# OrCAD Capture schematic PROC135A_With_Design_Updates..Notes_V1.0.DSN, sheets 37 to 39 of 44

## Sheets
37 37. CSI INTERFACE: size C; title: CSI INTERFACE
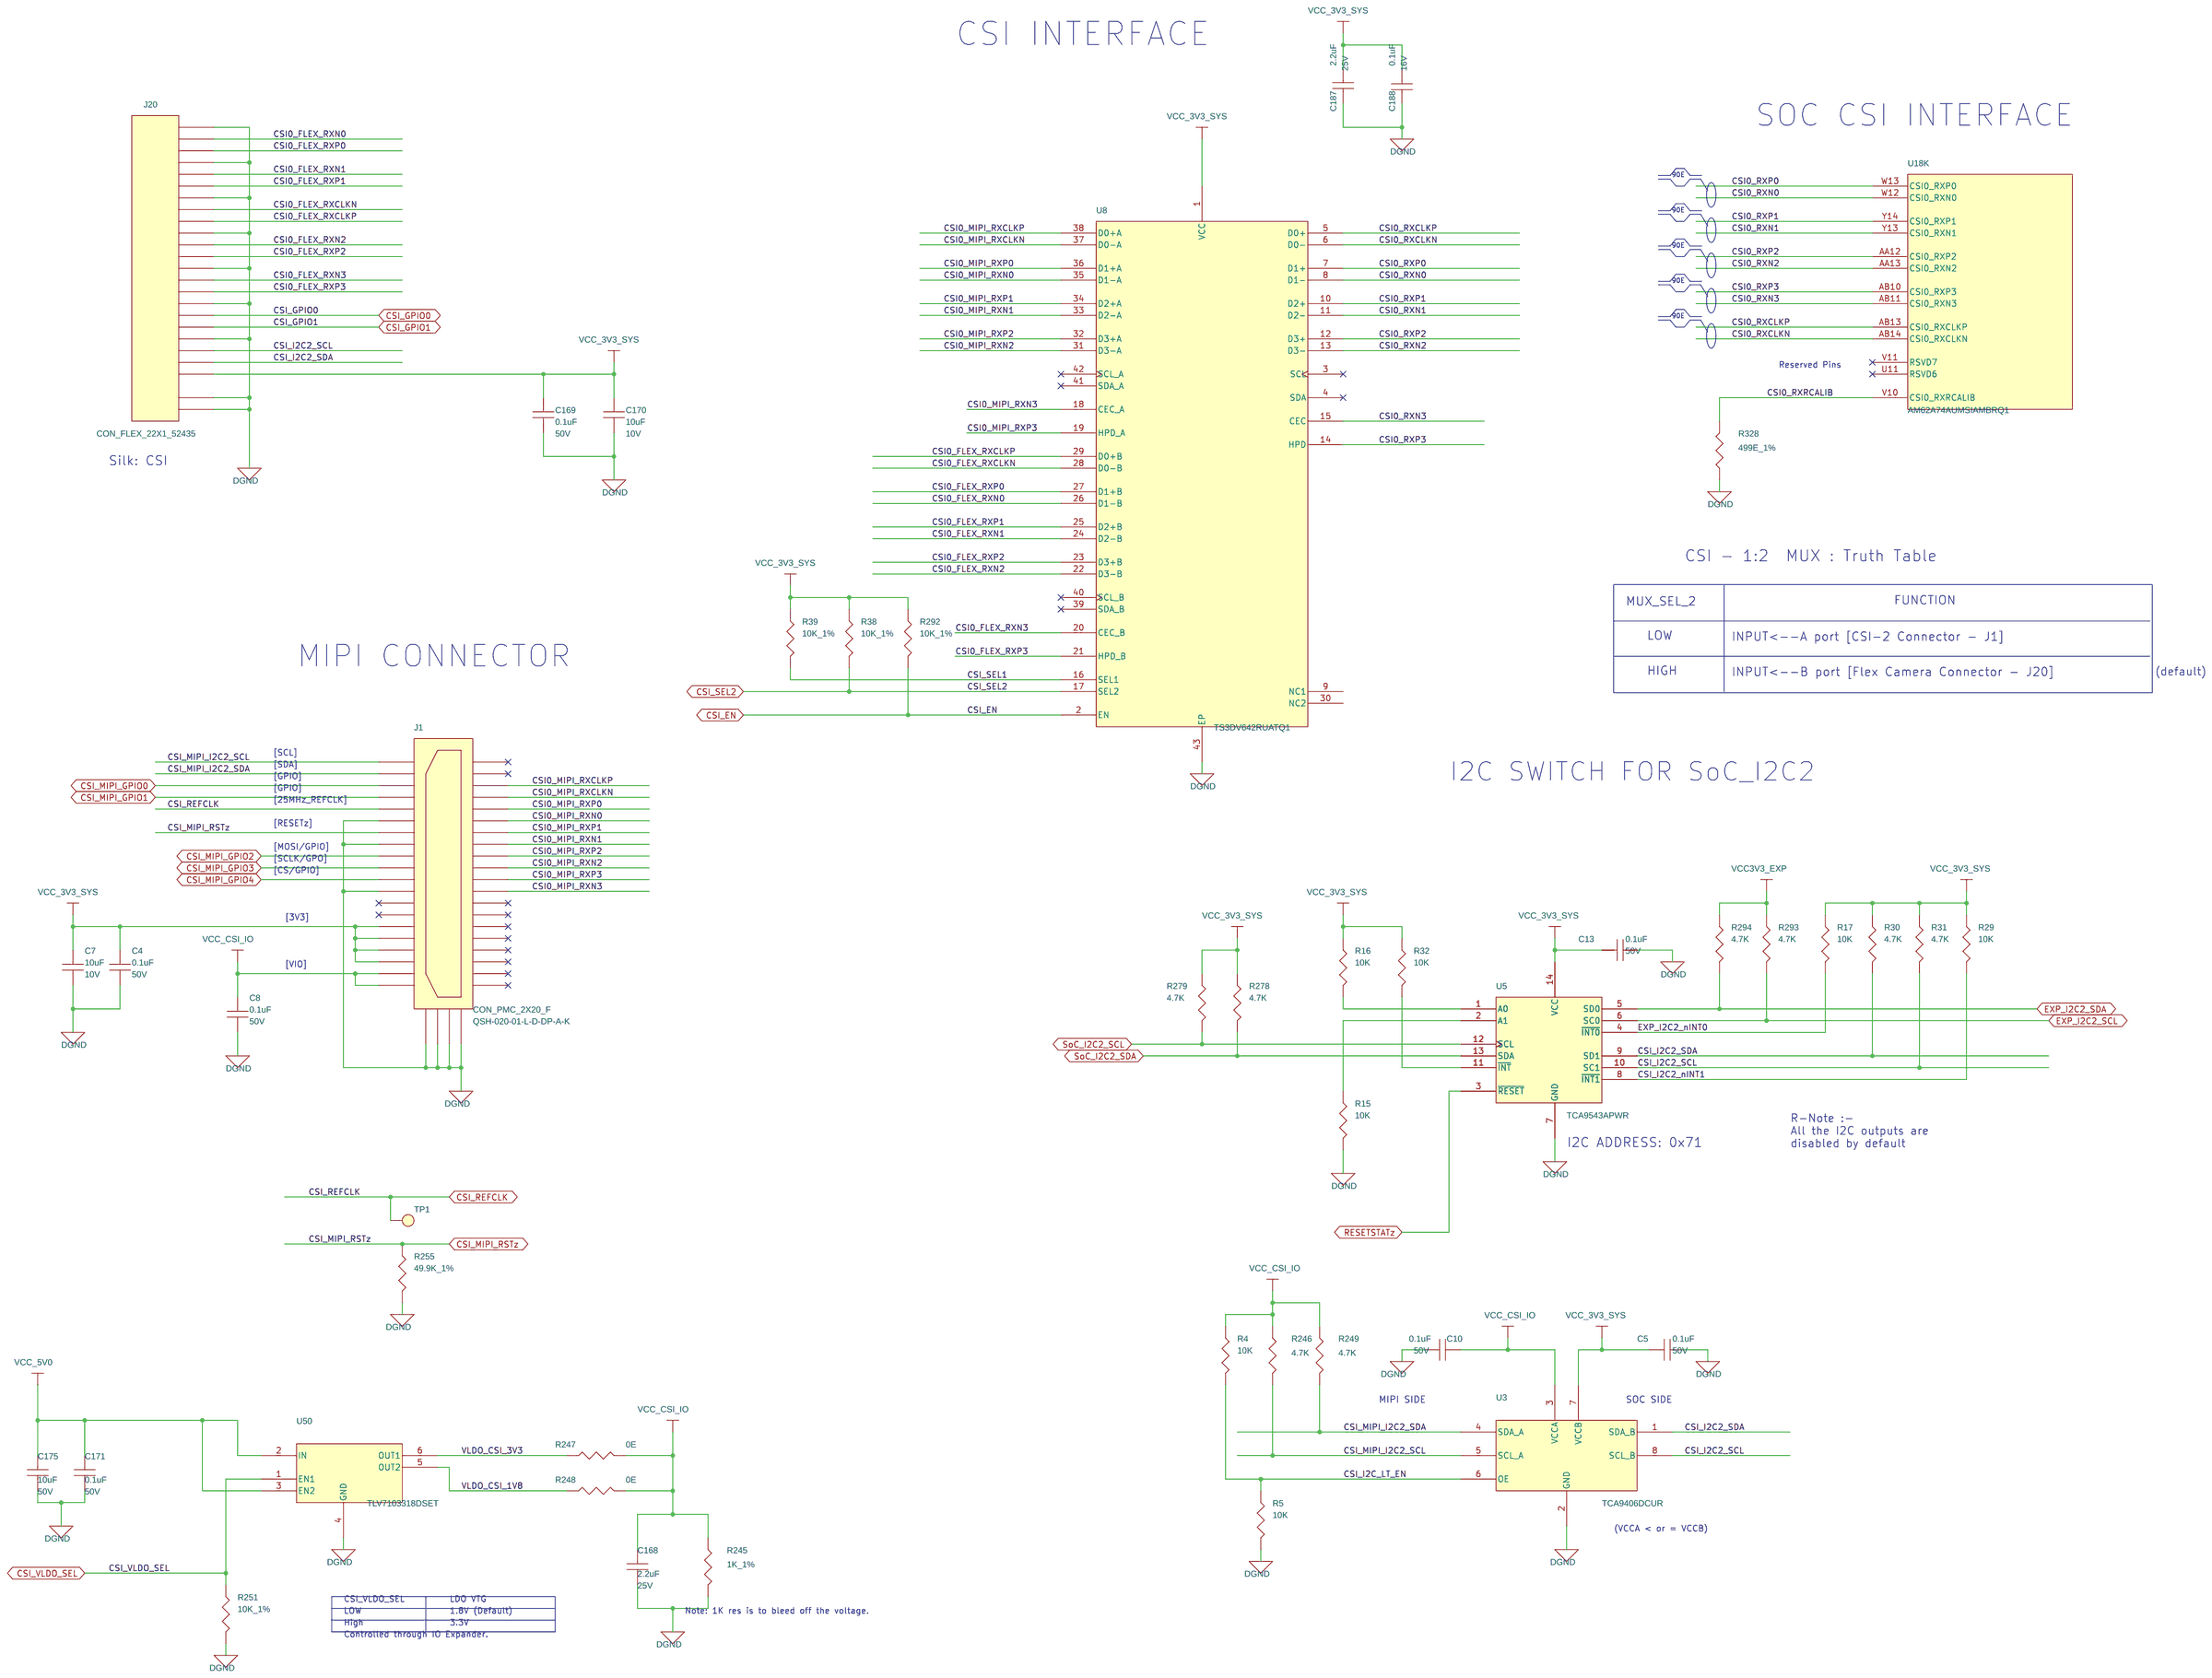
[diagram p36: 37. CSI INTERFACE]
38 38. AUDIO CODEC: size C; title: AUDIO CODEC
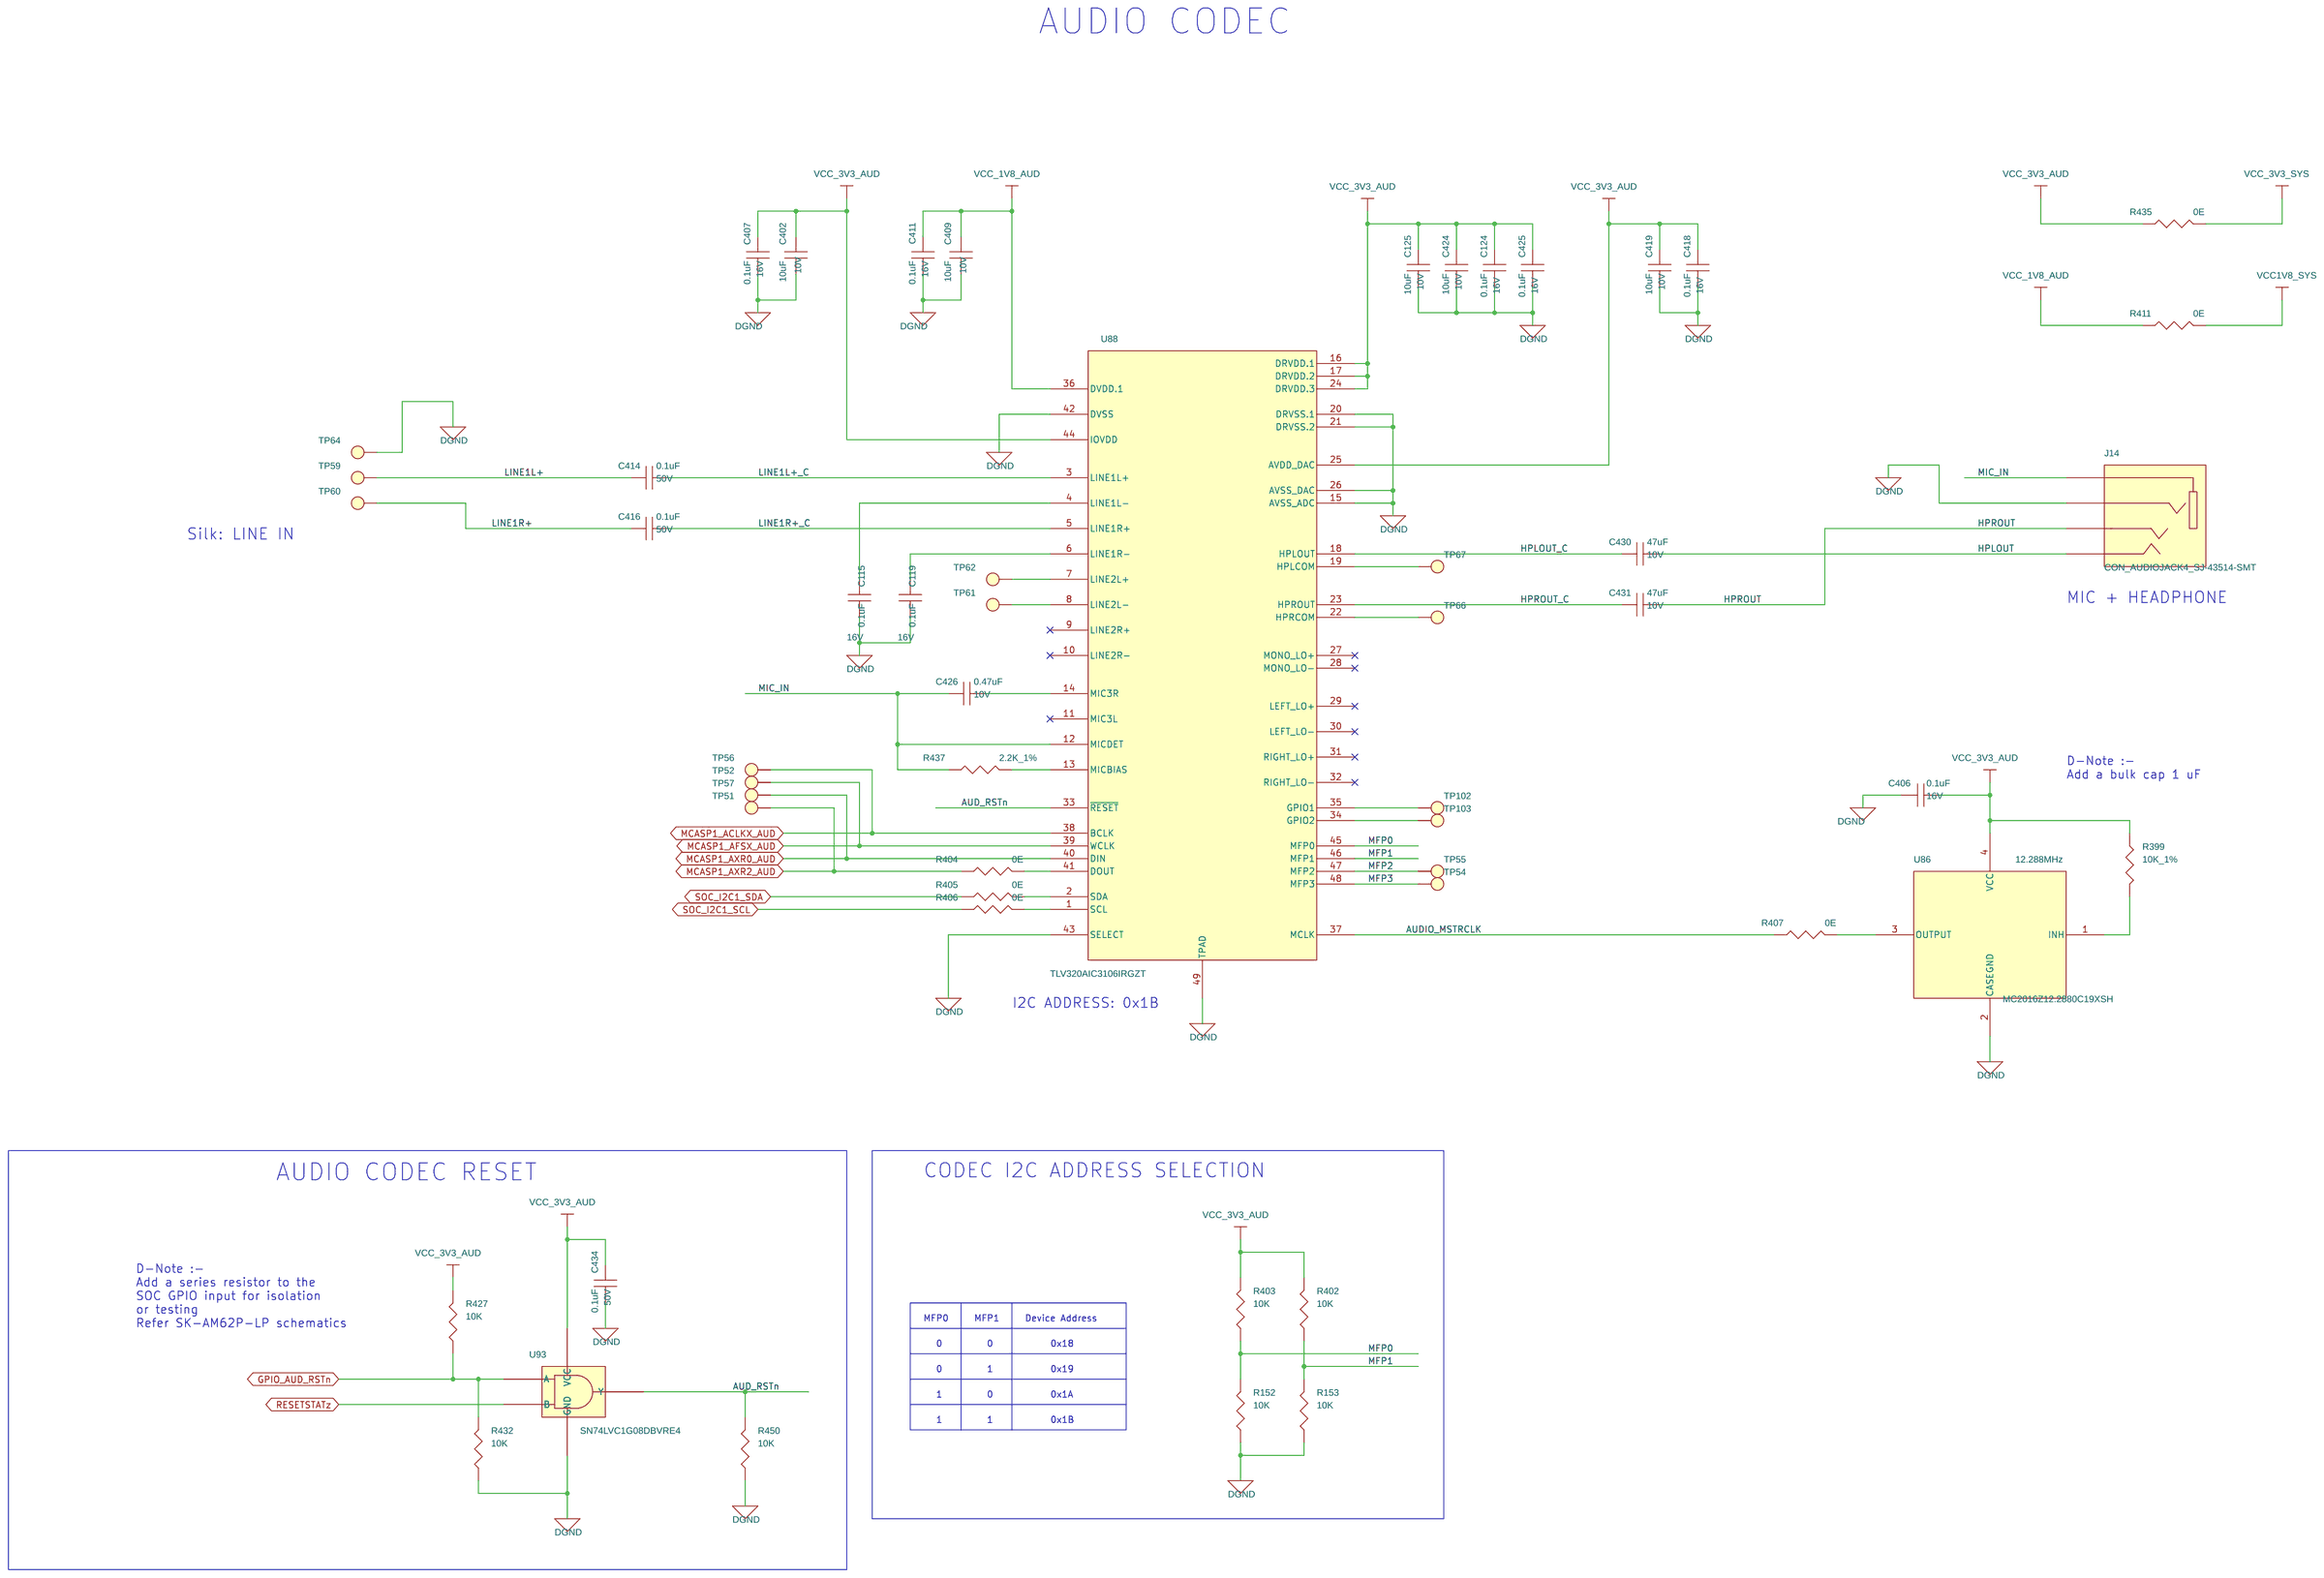
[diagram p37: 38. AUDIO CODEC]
39 39. IO EXPANDER: size C; title: IO EXPANDER
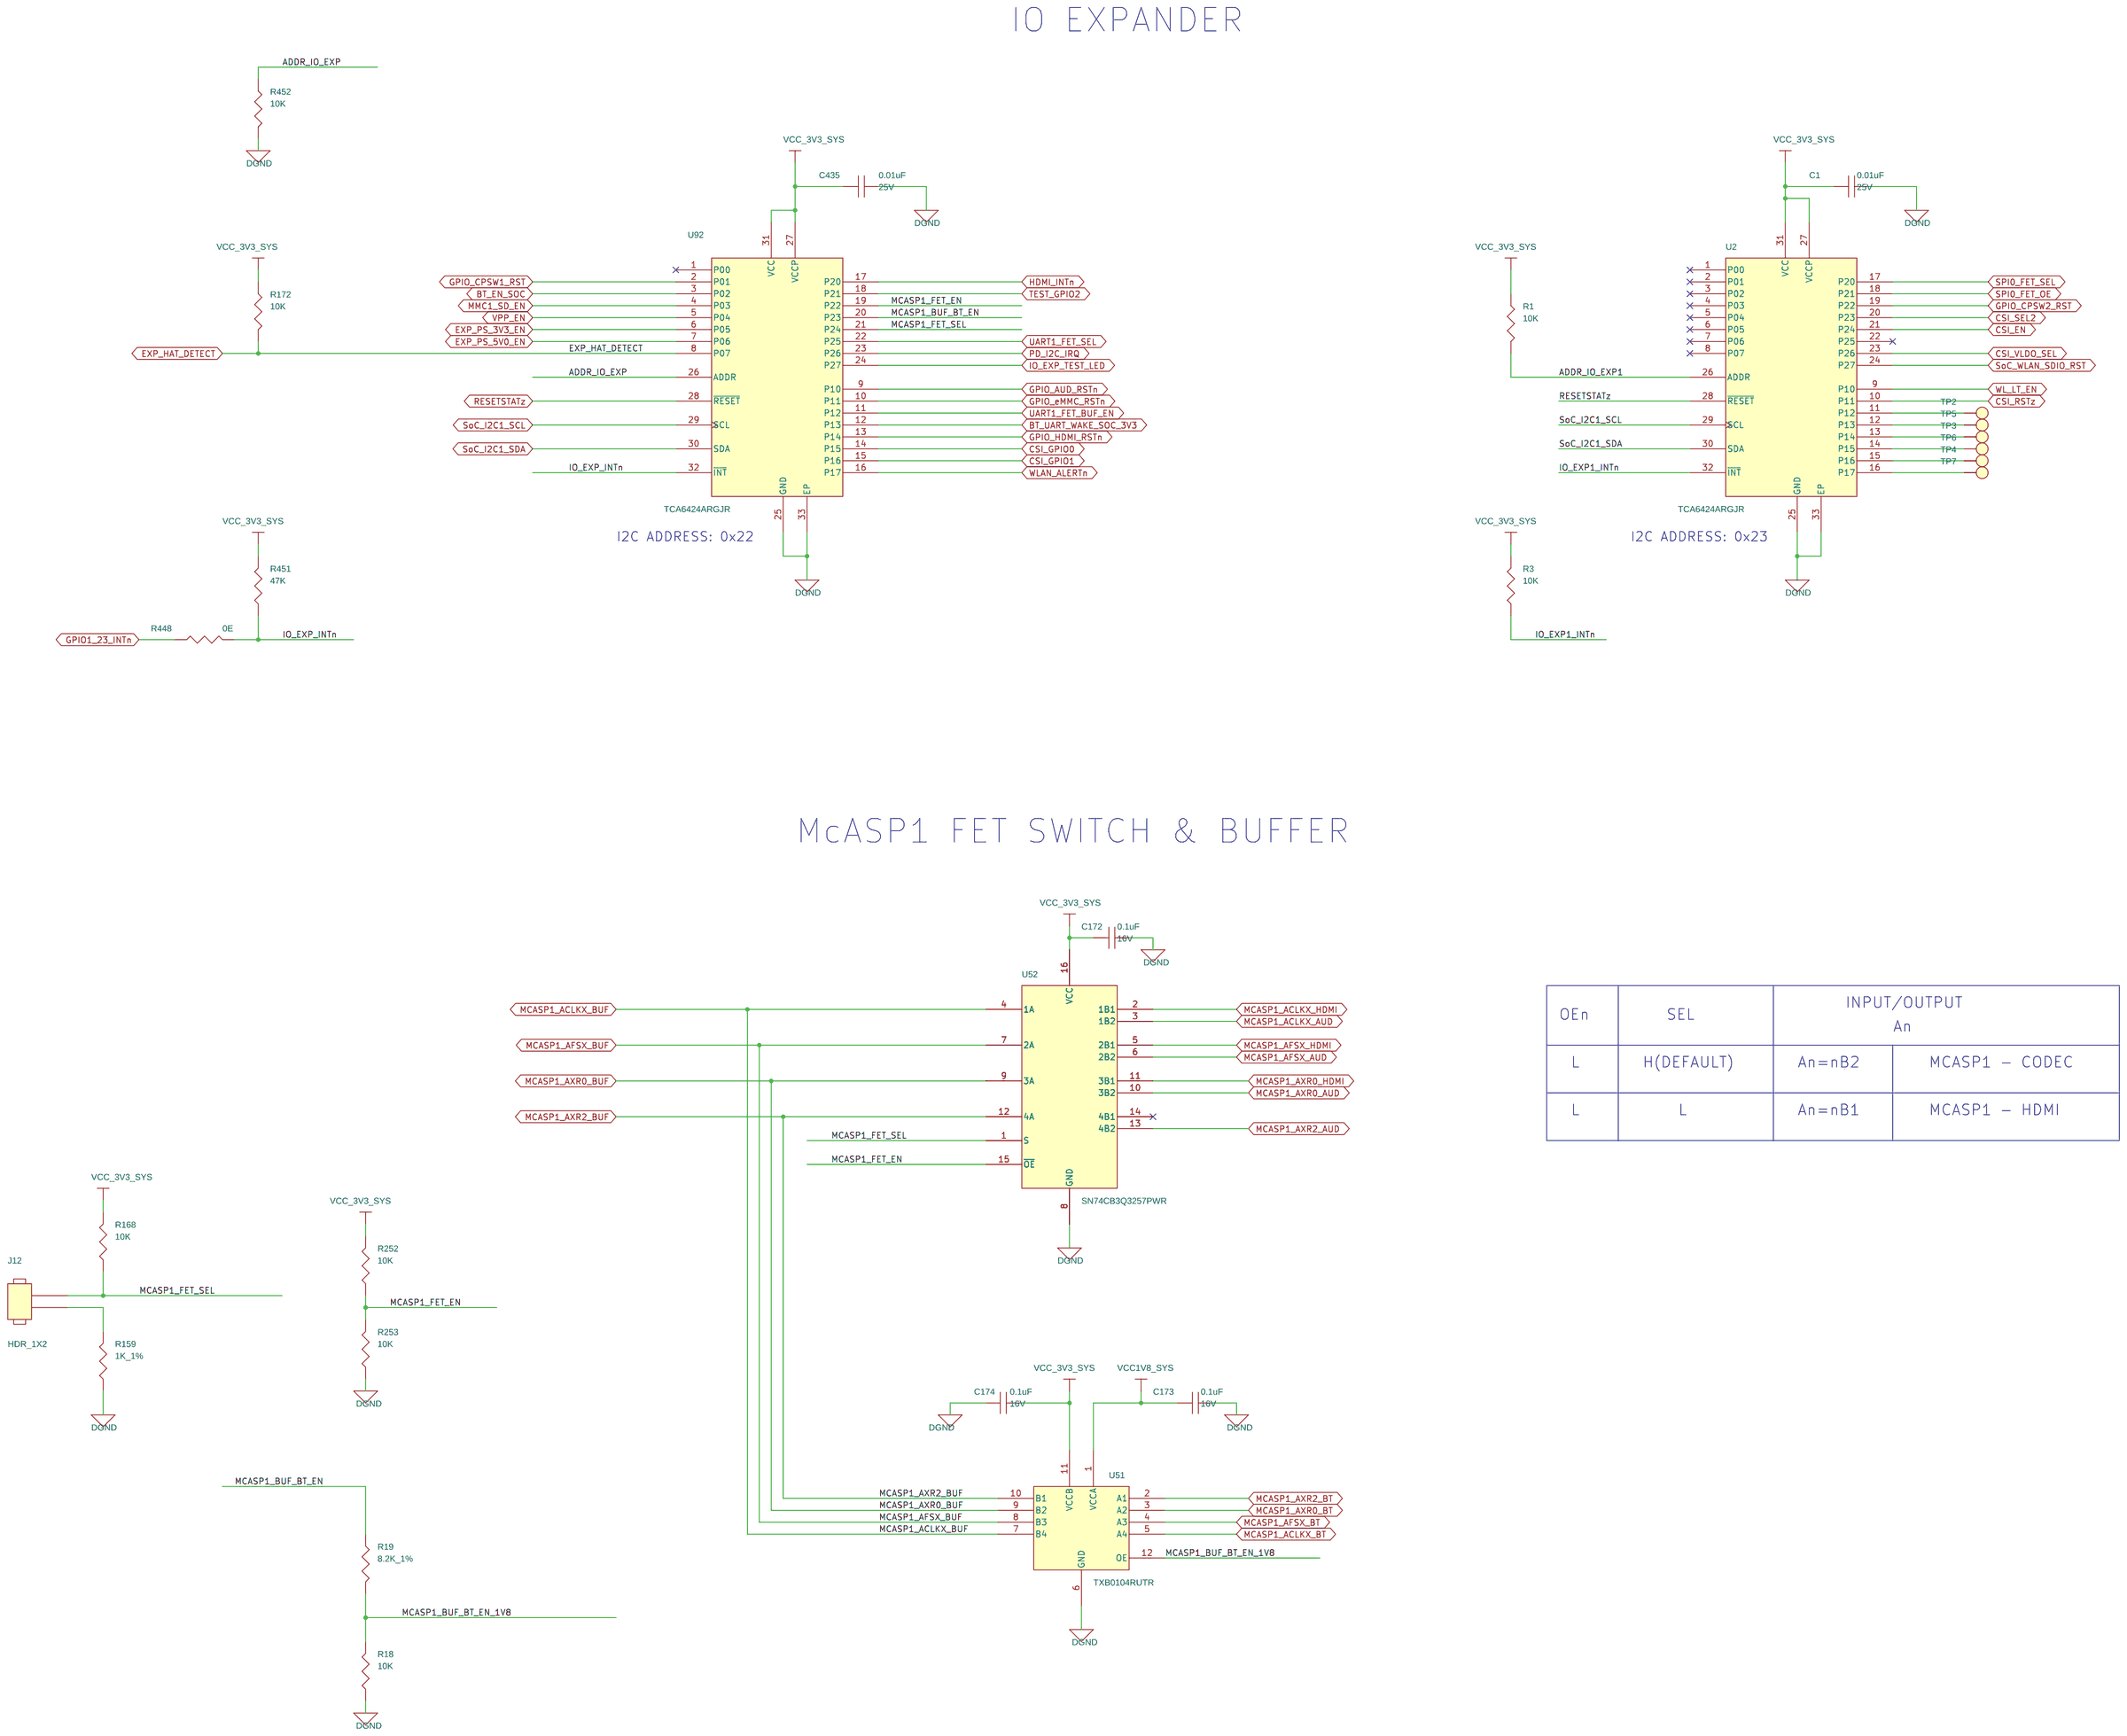
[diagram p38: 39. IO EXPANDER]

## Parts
sheet 37. CSI INTERFACE
C4  0.1uF  [CAP0402_0-75]
C5  0.1uF  [CAP0402_0-75]
C7  10uF  [CAP0402_0-75]
C8  0.1uF  [CAP0402_0-75]
C10  0.1uF  [CAP0402_0-75]
C13  0.1uF  [CAP0402_0-75]
C168  2.2uF  [CAP0402_0-75]
C169  0.1uF  [CAP0402_0-75]
C170  10uF  [CAP0402_0-75]
C171  0.1uF  [CAP0402_0-75]
C175  10uF  [CAP0805_1-5]
C187  2.2uF  [CAP0402_0-75]
C188  0.1uF  [CAP0201_0-5]
J1  CON_PMC_2X20_F  [CON_PMC2X20_QSH-020-01-D-DP-A_S_S_S_3-4]
J20  CON_FLEX_22X1_52435  [CON_FLEX22X1_52435_S_R_S]
R4  10K  [RES0201_0-5]
R5  10K  [RES0201_0-5]
R15  10K  [RES0201_0-5]
R16  10K  [RES0201_0-5]
R17  10K  [RES0201_0-5]
R29  10K  [RES0201_0-5]
R30  4.7K  [RES0201_0-5]
R31  4.7K  [RES0201_0-5]
R32  10K  [RES0201_0-5]
R38  10K_1%  [RES0402_0-5]
R39  10K_1%  [RES0402_0-5]
R245  1K_1%  [RES0402_0-5]
R246  4.7K  [RES0201_0-5]
R247  0E  [RES0402_0-5]
R248  0E  [RES0402_0-5]
R249  4.7K  [RES0201_0-5]
R251  10K_1%  [RES0402_0-5]
R255  49.9K_1%  [RES0402_0-5]
R278  4.7K  [RES0201_0-5]
R279  4.7K  [RES0201_0-5]
R292  10K_1%  [RES0402_0-5]
R293  4.7K  [RES0201_0-5]
R294  4.7K  [RES0201_0-5]
R328  499E_1%  [RES0402_0-5]
TP1  TP20_SMD  [TP20_SMD]
U3  TCA9406DCUR  [VSSOP8_19-68_85X95]
U5  TCA9543APWR  [TSSOP14_25-59_205X180_1-2]
U8  TS3DV642RUATQ1  [TQFN42_19-68_140X360_0-8]
U50  TLV7103318DSET  [WSON6_19-68_60X60]
sheet 38. AUDIO CODEC
C115  0.1uF  [CAP0201_0-5]
C119  0.1uF  [CAP0201_0-5]
C124  0.1uF  [CAP0201_0-5]
C125  10uF  [CAP0402_0-75]
C402  10uF  [CAP0402_0-75]
C406  0.1uF  [CAP0201_0-5]
C407  0.1uF  [CAP0201_0-5]
C409  10uF  [CAP0402_0-75]
C411  0.1uF  [CAP0201_0-5]
C414  0.1uF  [CAP0402_0-75]
C416  0.1uF  [CAP0402_0-75]
C418  0.1uF  [CAP0201_0-5]
C419  10uF  [CAP0402_0-75]
C424  10uF  [CAP0402_0-75]
C425  0.1uF  [CAP0201_0-5]
C426  0.47uF  [CAP0402_0-75]
C430  47uF  [CAP1206_2]
C431  47uF  [CAP1206_2]
C434  0.1uF  [CAP0402_0-75]
J14  CON_AUDIOJACK4_SJ-43514-SMT  [CON_AV4_SJ-43514-SMT_S_R_S_5-1]
R152  10K  [RES0201_0-5]
R153  10K  [RES0201_0-5]
R399  10K_1%  [RES0201_0-5]
R402  10K  [RES0201_0-5]
R403  10K  [RES0201_0-5]
R404  0E  [RES0201_0-5]
R405  0E  [RES0201_0-5]
R406  0E  [RES0201_0-5]
R407  0E  [RES0201_0-5]
R411  0E  [RES0402_0-5]
R427  10K  [RES0201_0-5]
R432  10K  [RES0201_0-5]
R435  0E  [RES0402_0-5]
R437  2.2K_1%  [RES0201_0-5]
R450  10K  [RES0201_0-5]
TP51  TP20_SMD  [TP20_SMD]
TP52  TP20_SMD  [TP20_SMD]
TP54  TP20_SMD  [TP20_SMD]
TP55  TP20_SMD  [TP20_SMD]
TP56  TP20_SMD  [TP20_SMD]
TP57  TP20_SMD  [TP20_SMD]
TP59  THRU HOLE  [TP_40X65]
TP60  THRU HOLE  [TP_40X65]
TP61  TP20_SMD  [TP20_SMD]
TP62  TP20_SMD  [TP20_SMD]
TP64  THRU HOLE  [TP_40X65]
TP66  TP20_SMD  [TP20_SMD]
TP67  TP20_SMD  [TP20_SMD]
TP102  TP20_SMD  [TP20_SMD]
TP103  TP20_SMD  [TP20_SMD]
U86  12.288MHz  [OSC4_KC2016K_80X60_SMD_0-8]
U88  TLV320AIC3106IRGZT  [VQFN48_19-68_285X285]
U93  SN74LVC1G08DBVRE4  [SOT23-5]
sheet 39. IO EXPANDER
C1  0.01uF  [CAP0201_0-5]
C172  0.1uF  [CAP0201_0-5]
C173  0.1uF  [CAP0201_0-5]
C174  0.1uF  [CAP0201_0-5]
C435  0.01uF  [CAP0201_0-5]
J12  HDR_1X2  [HDR_1X2_90120-0122_S_T_5-6]
R1  10K  [RES0201_0-5]
R3  10K  [RES0201_0-5]
R18  10K  [RES0201_0-5]
R19  8.2K_1%  [RES0201_0-5]
R159  1K_1%  [RES0402_0-5]
R168  10K  [RES0201_0-5]
R172  10K  [RES0201_0-5]
R252  10K  [RES0201_0-5]
R253  10K  [RES0201_0-5]
R448  0E  [RES0201_0-5]
R451  47K  [RES0201_0-5]
R452  10K  [RES0201_0-5]
TP2  TP20_SMD  [TP20_SMD]
TP3  TP20_SMD  [TP20_SMD]
TP4  TP20_SMD  [TP20_SMD]
TP5  TP20_SMD  [TP20_SMD]
TP6  TP20_SMD  [TP20_SMD]
TP7  TP20_SMD  [TP20_SMD]
U2  TCA6424ARGJR  [QFN32_19-68_200X200]
U51  TXB0104RUTR  [UQFN12_TXB0104RUT_70X80_0-6]
U52  SN74CB3Q3257PWR  [TSSOP16_25-59_205X180]
U92  TCA6424ARGJR  [QFN32_19-68_200X200]
sheet 41. OSCILLATOR
U18  AM62A74AUMSIAMBRQ1  [FBGA484_31-49_710X710_2-7]  (sections A,B,C,D,E,F,G,H,I,J,K,L,M,N,O,P,Q)

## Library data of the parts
C4 C5 C8 C10 C13 C169 C171 = CAP: CAP CERAMIC 0.1uF 50V 10% X7R 0402; Alt_Mfr_name: YAGEO AMERICA; Alt_Mfr_part_number: CC0402KRX5R8BB104; Chkd/date: MANIRAJA/261020; Crtd /date: ALVY/211020; Custom_Duty: 15%; Customs_HS_Code: 85322990; Distributor_name: DIGIKEY; Distributor_part_number: 490-10700-1-ND; Footprint Path: Y:\MIS_DATABASE\Library\ALTIUM_TOOL\PCB_FOOTPRINTS\Altium_Footprint_Lib.PcbLib; Height: 0.55MM; Library Path: Y:\MIS_DATABASE\Library\ALTIUM_TOOL\SCHEMATICS_PARTS\MS_DISCRETE_Library.schlib; Mfr_name: MURATA; Mfr_part_number: GRM155R71H104KE14D; Mistral Part No: 120011100014-R; Package: 0402; Part_type: CAPACITORS\CERAMIC; Project: J7_CP; RoHS: RoHS; Temperature: -55°C+125°C; Tolerance: 10%; Voltage: 50V; Wattage: NA; Weight: 3.1mg; Datasheet: Y:\MIS_DATABASE\DATASHEETS\CAPACITORS\GRM155R71H104KE14.PDF
C7 C125 C170 C402 C409 C419 C424 = CAP: CAP CERAMIC 10uF 10V 20% X5R 0402; Chkd/date: MANIRAJA/300520; Crtd /date: ALVY/260520; Custom_Duty: 15%; Customs_HS_Code: 85322990; Distributor_name: DIGIKEY; Distributor_part_number: 490-GRM155R61A106ME11DTR-ND; Footprint Path: Y:\MIS_DATABASE\Library\ALTIUM_TOOL\PCB_FOOTPRINTS\Altium_Footprint_Lib.PcbLib; Height: 0.55MM; Library Path: Y:\MIS_DATABASE\Library\ALTIUM_TOOL\SCHEMATICS_PARTS\MS_DISCRETE_Library.schlib; Mfr_name: MURATA; Mfr_part_number: GRM155R61A106ME11D; Mistral Part No: 120013110019-R; Package: 0402; Part_type: CAPACITORS\CERAMIC; Project: QCS610_NANOSOM; RoHS: RoHS; Temperature: -55°C+85°C; Tolerance: 20%; Voltage: 10V; Wattage: NA; Weight: 3.1mg; Datasheet: Y:\MIS_DATABASE\DATASHEETS\CAPACITORS\MURATA-GXX-SER_NOV17.PDF
C168 = CAP: CAP CERAMIC 2.2uF 25V 10% X5R 0402; Chkd/date: ALVY/010721; Crtd /date: MANIRAJA/010721; Custom_Duty: 15%; Customs_HS_Code: 85322990; Distributor_name: DIGIKEY; Distributor_part_number: 490-12703-1-ND; Footprint Path: Y:\MIS_DATABASE\Library\ALTIUM_TOOL\PCB_FOOTPRINTS\Altium_Footprint_Lib.PcbLib; Height: 0.70MM; Library Path: Y:\MIS_DATABASE\Library\ALTIUM_TOOL\SCHEMATICS_PARTS\MS_DISCRETE_Library.schlib; Manufacturer: MURATA; Mfr_name: MURATA; Mfr_part_number: GRM155R61E225KE11D; Mistral Part No: 120015120001-R; Package: 0402; Part_type: CAPACITORS\CERAMIC; Project: TI_AM263X_CC; RoHS: RoHS; Temperature: -55°C+85°C; Tolerance: 10%; Voltage: 25V; Wattage: NA; Weight: 1.5mg; Datasheet: Y:\MIS_DATABASE\DATASHEETS\CAPACITORS\GRM155R61E225KE11.PDF
C175 = CAP: CAP CERAMIC 10uF 50V 10% X5R 0805; Chkd/date: MANIRAJA/010321; Crtd /date: ALVY/010321; Custom_Duty: 15%; Customs_HS_Code: 85322990; Distributor_name: DIGIKEY; Distributor_part_number: 490-18663-1-ND; Footprint Path: Y:\MIS_DATABASE\Library\ALTIUM_TOOL\PCB_FOOTPRINTS\Altium_Footprint_Lib.PcbLib; Height: 1.45MM; Library Path: Y:\MIS_DATABASE\Library\ALTIUM_TOOL\SCHEMATICS_PARTS\MS_DISCRETE_Library.schlib; Manufacturer: MURATA; Mfr_name: MURATA; Mfr_part_number: GRM21BR61H106KE43L; Mistral Part No: 120021030002-R; Package: 0805; Part_type: CAPACITORS\CERAMIC; Project: J7ES_SK_BRD; RoHS: RoHS; Temperature: -55°C+85°C; Tolerance: 10%; Voltage: 50V; Wattage: NA; Weight: 6.4mg; Datasheet: Y:\MIS_DATABASE\DATASHEETS\CAPACITORS\GRM21BR61H106KE43.PDF
C187 = CAP: CAP CERAMIC 2.2uF 25V 10% X5R 0402; Chkd/date: ALVY/010721; Crtd /date: MANIRAJA/010721; Custom_Duty: 15%; Customs_HS_Code: 85322990; Distributor_name: DIGIKEY; Distributor_part_number: 490-12703-1-ND; Footprint Path: Y:\MIS_DATABASE\Library\ALTIUM_TOOL\PCB_FOOTPRINTS\Altium_Footprint_Lib.PcbLib; Height: 0.70MM; Library Path: Y:\MIS_DATABASE\Library\ALTIUM_TOOL\SCHEMATICS_PARTS\MS_DISCRETE_Library.schlib; Mfr_name: MURATA; Mfr_part_number: GRM155R61E225KE11D; Mistral Part No: 120015120001-R; Package: 0402; Part_type: CAPACITORS\CERAMIC; Project: TI_AM263X_CC; RoHS: RoHS; Temperature: -55°C+85°C; Tolerance: 10%; Voltage: 25V; Wattage: NA; Weight: 1.5mg; Datasheet: Y:\MIS_DATABASE\DATASHEETS\CAPACITORS\GRM155R61E225KE11.PDF
C172-C174 C188 = CAP: CAP CERAMIC 0.1uF 16V 10% X5R 0201; Alt_Mfr_name: YAGEO AMERICA; Alt_Mfr_part_number: CC0402KRX5R8BB104; Chkd/date: MANIRAJA/230118; Crtd /date: MANIRAJA/230118; Custom_Duty: 15%; Customs_HS_Code: 85322990; Distributor_name: DIGIKEY; Distributor_part_number: 490-14305-1-ND; Footprint Path: Y:\MIS_DATABASE\Library\ALTIUM_TOOL\PCB_FOOTPRINTS\Altium_Footprint_Lib.PcbLib; Height: 0.33MM; Library Path: Y:\MIS_DATABASE\Library\ALTIUM_TOOL\SCHEMATICS_PARTS\MS_DISCRETE_Library.schlib; Mfr_name: MURATA; Mfr_part_number: GRM033R61C104KE14D; Mistral Part No: 120009030072-R; Package: 0201; Part_type: CAPACITORS\CERAMIC; Project: TI_MAXIE_CPB; RoHS: RoHS; Temperature: -55°C+85°C; Tolerance: 10%; Voltage: 16V; Wattage: NA; Weight: 0.33mg; Datasheet: Y:\MIS_DATABASE\DATASHEETS\CAPACITORS\GRM033R61C104KE14.PDF
J1 = CON_PMC_20X2_F_DP_TI: CON PMC 2X20 0.50MM PITCH FEMALE ST SMD; Chkd/date: MANIRAJA/251018; Crtd /date: ALVY/251018; Custom_Duty: 24%; Customs_HS_Code: 85369090; Distributor_name: DIGIKEY; Distributor_part_number: SAM10648-ND; Footprint Path: Y:\MIS_DATABASE\Library\ALTIUM_TOOL\PCB_FOOTPRINTS\Altium_Footprint_Lib.PcbLib; Height: 3.33MM; Library Path: Y:\MIS_DATABASE\Library\ALTIUM_TOOL\SCHEMATICS_PARTS\MS_CONNECTOR_Library.schlib; Library Ref: CON_PMC_20X2_F_DP; Mfr_name: SAMTEC; Mfr_part_number: QSH-020-01-L-D-DP-A-K; Mistral Part No: 150018100049-R; Package: SMD; Part_type: CONNECTOR\PMC; Project: TI_J7ES_EVM_CP; RoHS: RoHS; Temperature: -55°C+125°C; Tolerance: NA; Voltage: NA; Wattage: NA; Weight: NA; Datasheet: Y:\MIS_DATABASE\DATASHEETS\CONNECTORS\QSH-SERIES.PDF
J20 = CON_22X1_2SH: CON FPC 22X1 0.50MM PITCH TPM RT SMD; Chkd/date: PRAVEEN/090822; Crtd /date: PRAVEEN/090822; Custom_Duty: 24%; Customs_HS_Code: 85369090; Distributor_name: DIGIKEY; Distributor_part_number: WM6753CT-ND; Height: 2.00MM; Mfr_name: MOLEX; Mfr_part_number: 52435-2271; Mistral Part No: 150022080019-R; Package: SMD; Part_type: CONNECTOR\FPC; Project: JHAHP_SVB; RoHS: RoHS; Temperature: -20°C to +85°C; Tolerance: NA; Voltage: NA; Wattage: NA; Datasheet: Y:\MIS_DATABASE\DATASHEETS\CONNECTORS\52435.PDF
R1 R3-R5 R15-R18 R29 R32 R152 R153 R168 R172 R252 R253 R402 R403 R427 R432 R450 R452 = RESISTOR: RES 10K 1/20W 5% 0201; Chkd/date: MANIRAJA/050517; Crtd /date: MANIRAJA/050517; Custom_Duty: 15%; Customs_HS_Code: 85332119; Distributor_name: DIGIKEY; Distributor_part_number: 311-10KNCT-ND; Footprint Path: Y:\MIS_DATABASE\Library\ALTIUM_TOOL\PCB_FOOTPRINTS\Altium_Footprint_Lib.PcbLib; Height: 0.26MM; Library Path: Y:\MIS_DATABASE\Library\ALTIUM_TOOL\SCHEMATICS_PARTS\MS_DISCRETE_Library.schlib; Mfr_name: YAGEO AMERICA; Mfr_part_number: RC0201JR-0710KL; Mistral Part No: 110010070051-R; Package: 0201; Part_type: RESISTORS\FIXED; Project: GOLDEN-I LITE; RoHS: RoHS; Temperature: -55°C+125°C; Tolerance: 5%; Voltage: NA; Wattage: 1/20W; Weight: 0.17mg; Datasheet: Y:\MIS_DATABASE\DATASHEETS\RESISTORS\RCXXXXL-SER_MAR18.PDF
R30 R31 R246 R249 R278 R279 R293 R294 = RESISTOR: RES 4.7K 1/20W 5% 0201; Chkd/date: MANIRAJA/200921; Crtd /date: ALVY/200921; Custom_Duty: 15%; Customs_HS_Code: 85332119; Distributor_name: DIGIKEY; Distributor_part_number: 311-4.7KNCT-ND; Footprint Path: Y:\MIS_DATABASE\Library\ALTIUM_TOOL\PCB_FOOTPRINTS\Altium_Footprint_Lib.PcbLib; Height: 0.26MM; Library Path: Y:\MIS_DATABASE\Library\ALTIUM_TOOL\SCHEMATICS_PARTS\MS_DISCRETE_Library.schlib; Mfr_name: YAGEO AMERICA; Mfr_part_number: RC0201JR-074K7L; Mistral Part No: 110021090007-R; Package: 0201; Part_type: RESISTORS\FIXED; Project: TI_AM62x SKEVM_BRD; RoHS: RoHS; Temperature: -55°C+125°C; Tolerance: 5%; Voltage: NA; Wattage: 1/20W; Weight: 0.17mg; Datasheet: Y:\MIS_DATABASE\DATASHEETS\RESISTORS\RCXXXXL-SER_MAR18.PDF
R38 R39 R251 R292 = RESISTOR: RES 10K 1/10W 1% AUTO 0402; Chkd/date: MANIRAJA/191020; Crtd /date: ALVY/191020; Custom_Duty: 15%; Customs_HS_Code: 85332119; Distributor_name: DIGIKEY; Distributor_part_number: MCS0402-10.0K-MFCT-ND; Footprint Path: Y:\MIS_DATABASE\Library\ALTIUM_TOOL\PCB_FOOTPRINTS\Altium_Footprint_Lib.PcbLib; Height: 0.37MM; Library Path: Y:\MIS_DATABASE\Library\ALTIUM_TOOL\SCHEMATICS_PARTS\MS_DISCRETE_Library.schlib; Manufacturer: VISHAY; Mfr_name: VISHAY; Mfr_part_number: MCS0402MC1002FE000; Mistral Part No: 110020100039-R; Package: 0402; Part_type: RESISTORS\FIXED; Project: MCX_80MHz_ADC_DRIVER; RoHS: RoHS; Temperature: -55°C+175°C; Tolerance: 1%; Voltage: NA; Wattage: 1/10W; Weight: 0.65mg; Datasheet: Y:\MIS_DATABASE\DATASHEETS\RESISTORS\MCTXXXXM-SER.PDF
R159 R245 = RESISTOR: RES 1K 1/10W 1% 0402; Chkd/date: VASANTHA/281216; Crtd /date: MAZHAR/150506; Custom_Duty: 15%; Customs_HS_Code: 85332119; Distributor_name: DIGIKEY; Distributor_part_number: P1.00KLCT-ND; Footprint Path: Y:\MIS_DATABASE\Library\ALTIUM_TOOL\PCB_FOOTPRINTS\Altium_Footprint_Lib.PcbLib; Height: 0.40MM; Library Path: Y:\MIS_DATABASE\Library\ALTIUM_TOOL\SCHEMATICS_PARTS\MS_DISCRETE_Library.schlib; Mfr_name: PANASONIC-ECG; Mfr_part_number: ERJ-2RKF1001X; Mistral Part No: 110009030411-R; Package: 0402; Part_type: RESISTORS\FIXED; Project: VOCERA; RoHS: RoHS; Temperature: -55°C+155°C; Tolerance: 1%; Voltage: NA; Wattage: 1/10W; Weight: 0.8mg; Datasheet: Y:\MIS_DATABASE\DATASHEETS\RESISTORS\PAN-ERJSER_NOV17.PDF
R247 R248 = RESISTOR: RES 0E 1/16W JUMPER 0402; Chkd/date: VASANTHA/201216; Crtd /date: MUDDU/190810; Custom_Duty: 15%; Customs_HS_Code: 85332119; Distributor_name: DIGIKEY; Distributor_part_number: 541-0.0JCT-ND; Footprint Path: Y:\MIS_DATABASE\Library\ALTIUM_TOOL\PCB_FOOTPRINTS\Altium_Footprint_Lib.PcbLib; Height: 0.40MM; Library Path: Y:\MIS_DATABASE\Library\ALTIUM_TOOL\SCHEMATICS_PARTS\MS_DISCRETE_Library.schlib; Manufacturer: VISHAY; Mfr_name: VISHAY; Mfr_part_number: CRCW04020000Z0ED; Mistral Part No: 110010080019-R; Package: 0402; Part_type: RESISTORS\FIXED; Project: PB_BUGBASE; RoHS: RoHS; Temperature: -55°C+155°C; Tolerance: NA; Voltage: NA; Wattage: 1/16W; Weight: 0.65mg; Datasheet: Y:\MIS_DATABASE\DATASHEETS\RESISTORS\CRCW0603.PDF
R255 = RESISTOR: RES 49.9K 1/10W 1% 0402; Chkd/date: MANIRAJA/130617; Crtd /date: BAVISH/020611; Custom_Duty: 15%; Customs_HS_Code: 85332119; Distributor_name: DIGIKEY; Distributor_part_number: P49.9KLCT-ND; Footprint Path: Y:\MIS_DATABASE\Library\ALTIUM_TOOL\PCB_FOOTPRINTS\Altium_Footprint_Lib.PcbLib; Height: 0.40MM; Library Path: Y:\MIS_DATABASE\Library\ALTIUM_TOOL\SCHEMATICS_PARTS\MS_DISCRETE_Library.schlib; Manufacturer: VISHAY; Mfr_name: PANASONIC-ECG; Mfr_part_number: ERJ-2RKF4992X; Mistral Part No: 110011060018-R; Package: 0402; Part_type: RESISTORS\FIXED; Project: AM4515_EVM_LCD; RoHS: RoHS; Temperature: -55°C+155°C; Tolerance: 1%; Voltage: NA; Wattage: 1/10W; Weight: 0.8mg; Datasheet: Y:\MIS_DATABASE\DATASHEETS\RESISTORS\PAN-ERJSER_NOV17.PDF
R328 = RESISTOR: RES 499E 1/16W 1% 0402; Chkd/date: MANIRAJA/051020; Crtd /date: ALVY/051020; Custom_Duty: 15%; Customs_HS_Code: 85332119; Distributor_name: DIGIKEY; Distributor_part_number: 311-499LRCT-ND; Footprint Path: Y:\MIS_DATABASE\Library\ALTIUM_TOOL\PCB_FOOTPRINTS\Altium_Footprint_Lib.PcbLib; Height: 0.40MM; Library Path: Y:\MIS_DATABASE\Library\ALTIUM_TOOL\SCHEMATICS_PARTS\MS_DISCRETE_Library.schlib; Mfr_name: YAGEO AMERICA; Mfr_part_number: RC0402FR-07499RL; Mistral Part No: 110020080006-R; Package: 0402; Part_type: RESISTORS\FIXED; Project: AM64XX_EVM; RoHS: RoHS; Temperature: -55°C+155°C; Tolerance: 1%; Voltage: NA; Wattage: 1/16W; Weight: 0.65mg; Datasheet: Y:\MIS_DATABASE\DATASHEETS\RESISTORS\RCXXXXL-SER_MAR18.PDF
TP1 TP51 TP52 TP54-TP57 TP61 TP62 TP66 TP67 TP102 TP103 = TESTPOINT: TESTPOINT CIR 20 SMD; Chkd/date: SHREESHAIL/171006; Crtd /date: MAZHAR/171006; Custom_Duty: NA; Customs_HS_Code: NA; Distributor_name: NA; Distributor_part_number: NA; Footprint Path: Y:\MIS_DATABASE\Library\ALTIUM_TOOL\PCB_FOOTPRINTS\Altium_Footprint_Lib.PcbLib; Height: NA; Library Path: Y:\MIS_DATABASE\Library\ALTIUM_TOOL\SCHEMATICS_PARTS\MS_DISCRETE_Library.schlib; MECHANICAL 3D STEP FILE: NA; Mfr_name: LOCAL; Mistral Part No: NA; Package: SMD; Project: BT MODULE_CSRBC04; RoHS: NA; Temperature: NA; Tolerance: NA; Voltage: NA; Wattage: NA; Weight: NA; Datasheet: NA
U3 = TCA9406DCUR_VSSOP8: IC VOLTAGE-LEVEL TRANSLATOR 2BIT BIDIRECTIONAL VSSOP8; Chkd/date: USMAN/190612; Crtd /date: BAVISH/210611; Custom_Duty: 15%; Customs_HS_Code: 85423100; Distributor_name: DIGIKEY; Distributor_part_number: 296-28109-1-ND; Footprint Path: Y:\MIS_DATABASE\Library\ALTIUM_TOOL\PCB_FOOTPRINTS\Altium_Footprint_Lib.PcbLib; Height: 0.90MM; Library Path: Y:\MIS_DATABASE\Library\ALTIUM_TOOL\SCHEMATICS_PARTS\MS_MISCINTERFACE_Library.schlib; Mfr_name: TEXAS INSTRUMENTS; Mistral Part No: 141011060026-R; Package: VSSOP8; Part_type: ICS\INTERFACE; Project: SVDU; RoHS: RoHS; Temperature: -40°C+85°C; Tolerance: NA; Voltage: NA; Wattage: NA; Weight: NA; Datasheet: Y:\MIS_DATABASE\DATASHEETS\ICS\INTERFACE\TCA9406.PDF
U5 = TCA9543APWR_TSSOP14: IC 2-CHANNEL I2C BUS SWITCH WITH INTERRUPT LOGIC AND RESET TSSOP14; Chkd/date: VASANTHA/060516; Crtd /date: VASANTHA/070316; Custom_Duty: 15%; Customs_HS_Code: 85423100; Distributor_name: DIGIKEY; Distributor_part_number: 296-42157-1-ND; Footprint Path: Y:\MIS_DATABASE\Library\ALTIUM_TOOL\PCB_FOOTPRINTS\Altium_Footprint_Lib.PcbLib; Height: 1.20MM; Library Path: Y:\MIS_DATABASE\Library\ALTIUM_TOOL\SCHEMATICS_PARTS\MS_BUSDRIVERTRANSCEIVER_Library.schlib; Manufacturer: TEXAS INSTRUMENTS; Mfr_name: TEXAS INSTRUMENTS; Mistral Part No: 141016030006-R; Package: TSSOP14; Part_type: ICS\DIGITAL\BUSTRANSCEIVER; Project: OCTASIC_3600; RoHS: RoHS; Temperature: -40°C+85°C; Tolerance: NA; Voltage: NA; Wattage: NA; Weight: NA; Datasheet: Y:\MIS_DATABASE\DATASHEETS\ICS\DIGITAL\BUSTRANSCEIVER\TCA9543A.PDF
U8 = TS3DV642-Q1_WQFN42: IC 8Gbps 12-CHANNEL DIFFERENTIAL 1:2 AND 2:1 MUX WQFN42; Chkd/date: MANIRAJA/170221; Crtd /date: ALVY/170221; Custom_Duty: 15%; Customs_HS_Code: 85423100; Distributor_name: NA; Distributor_part_number: NA; Footprint Path: Y:\MIS_DATABASE\Library\ALTIUM_TOOL\PCB_FOOTPRINTS\Altium_Footprint_Lib.PcbLib; Height: 0.80MM; Library Path: Y:\MIS_DATABASE\Library\ALTIUM_TOOL\SCHEMATICS_PARTS\MS_COMBINATIONAL_Library.schlib; Mfr_name: TEXAS INSTRUMENTS; Mistral Part No: 141021020023-R; Package: WQFN42; Part_type: ICS\DIGITAL\COMBINATIONAL; Project: J7ES_SK_BRD; RoHS: RoHS; Temperature: -40°C+105°C; Tolerance: NA; Voltage: NA; Wattage: NA; Weight: NA; Datasheet: Y:\MIS_DATABASE\DATASHEETS\ICS\DIGITAL\COMBINATIONAL\TS3DV642-Q1.PDF
U50 = TLV7103318D_WSON6: IC REGULATOR LDO LINEAR 200mA WSON6; Chkd/date: NAVEED/080415; Crtd /date: JEBRAN/300315; Custom_Duty: 15%; Customs_HS_Code: 85423100; Distributor_name: DIGIKEY; Distributor_part_number: 296-29058-1-ND; Height: 0.80MM; Manufacturer: TEXAS INSTRUMENTS; Mfr_name: TEXAS INSTRUMENTS; Mistral Part No: 142015030017-R; Package: WSON6; Part_type: ICS\POWER\VOLTAGE REGULATOR; Project: DUET BOARDS; RoHS: RoHS; Temperature: -40°C+125°C; Tolerance: NA; Voltage: NA; Wattage: NA; Weight: NA; Datasheet: Y:\MIS_DATABASE\DATASHEETS\MISC\REGULATORS\TLV71-SER.PDF
C115 C119 C124 C406 C407 C411 C418 C425 = CAP: CAP CERAMIC 0.1uF 16V 10% X5R 0201; Chkd/date: MANIRAJA/230118; Crtd /date: MANIRAJA/230118; Custom_Duty: 15%; Customs_HS_Code: 85322990; Distributor_name: DIGIKEY; Distributor_part_number: 490-14305-1-ND; Footprint Path: Y:\MIS_DATABASE\Library\ALTIUM_TOOL\PCB_FOOTPRINTS\Altium_Footprint_Lib.PcbLib; Height: 0.33MM; Library Path: Y:\MIS_DATABASE\Library\ALTIUM_TOOL\SCHEMATICS_PARTS\MS_DISCRETE_Library.schlib; Mfr_name: MURATA; Mfr_part_number: GRM033R61C104KE14D; Mistral Part No: 120009030072-R; Package: 0201; Part_type: CAPACITORS\CERAMIC; Project: TI_MAXIE_CPB; RoHS: RoHS; Temperature: -55°C+85°C; Tolerance: 10%; Voltage: 16V; Wattage: NA; Weight: 0.33mg; Datasheet: Y:\MIS_DATABASE\DATASHEETS\CAPACITORS\GRM033R61C104KE14.PDF
C414 C416 C434 = CAP: CAP CERAMIC 0.1uF 50V 10% X7R 0402; Chkd/date: MANIRAJA/261020; Crtd /date: ALVY/211020; Custom_Duty: 15%; Customs_HS_Code: 85322990; Distributor_name: DIGIKEY; Distributor_part_number: 490-10700-1-ND; Footprint Path: Y:\MIS_DATABASE\Library\ALTIUM_TOOL\PCB_FOOTPRINTS\Altium_Footprint_Lib.PcbLib; Height: 0.55MM; Library Path: Y:\MIS_DATABASE\Library\ALTIUM_TOOL\SCHEMATICS_PARTS\MS_DISCRETE_Library.schlib; Mfr_name: MURATA; Mfr_part_number: GRM155R71H104KE14D; Mistral Part No: 120011100014-R; Package: 0402; Part_type: CAPACITORS\CERAMIC; Project: J7_CP; RoHS: RoHS; Temperature: -55°C+125°C; Tolerance: 10%; Voltage: 50V; Wattage: NA; Weight: 3.1mg; Datasheet: Y:\MIS_DATABASE\DATASHEETS\CAPACITORS\GRM155R71H104KE14.PDF
C426 = CAP: CAP CERAMIC 0.47uF 10V 10% X7R 0402; Chkd/date: MANIRAJA/310821; Crtd /date: ALVY/310821; Custom_Duty: 15%; Customs_HS_Code: 85322990; Distributor_name: DIGIKEY; Distributor_part_number: 490-14366-1-ND; Footprint Path: Y:\MIS_DATABASE\Library\ALTIUM_TOOL\PCB_FOOTPRINTS\Altium_Footprint_Lib.PcbLib; Height: 0.55MM; Library Path: Y:\MIS_DATABASE\Library\ALTIUM_TOOL\SCHEMATICS_PARTS\MS_DISCRETE_Library.schlib; Mfr_name: MURATA; Mfr_part_number: GRM155R71A474KE01D; Mistral Part No: 120021060019-R; Package: 0402; Part_type: CAPACITORS\CERAMIC; Project: TI_AM335x SK_BRD; RoHS: RoHS; Temperature: -55°C+125°C; Tolerance: 10%; Voltage: 10V; Wattage: NA; Weight: 1.5mg; Datasheet: Y:\MIS_DATABASE\DATASHEETS\CAPACITORS\GRM155R71A474KE01.PDF
C430 C431 = CAP: CAP CERAMIC 47uF 10V 20% X5R 1206; Chkd/date: USMAN/121213; Crtd /date: USMAN/121213; Custom_Duty: 15%; Customs_HS_Code: 85322990; Distributor_name: DIGIKEY; Distributor_part_number: 490-5528-1-ND; Footprint Path: Y:\MIS_DATABASE\Library\ALTIUM_TOOL\PCB_FOOTPRINTS\Altium_Footprint_Lib.PcbLib; Height: 1.80MM; Library Path: Y:\MIS_DATABASE\Library\ALTIUM_TOOL\SCHEMATICS_PARTS\MS_DISCRETE_Library.schlib; Mfr_name: MURATA; Mfr_part_number: GRM31CR61A476ME15L; Mistral Part No: 120013120015-R; Package: 1206; Part_type: CAPACITORS\CERAMIC; Project: DMP; RoHS: RoHS; Temperature: -55°C+85°C; Tolerance: 20%; Voltage: 10V; Wattage: NA; Weight: 40mg; Datasheet: Y:\MIS_DATABASE\DATASHEETS\CAPACITORS\MURATA-GXX-SER_NOV17.PDF
J14 = CON_AUDIOJACK4_SJ-43514-SMT: CON AUDIO JACK 4POS FEMALE RT SMD; Chkd/date: MAZHAR/230211; Crtd /date: MUDDU/300610; Custom_Duty: 24%; Customs_HS_Code: 85369090; Distributor_name: DIGIKEY; Distributor_part_number: CP-43514SJCT-ND; Footprint Path: Y:\MIS_DATABASE\Library\ALTIUM_TOOL\PCB_FOOTPRINTS\Altium_Footprint_Lib.PcbLib; Height: 5.10MM; Library Path: Y:\MIS_DATABASE\Library\ALTIUM_TOOL\SCHEMATICS_PARTS\MS_CONNECTOR_Library.schlib; Mfr_name: CUI INC; Mfr_part_number: SJ-43514-SMT-TR; Mistral Part No: 150010060028-R; Package: SMD; Part_type: CONNECTOR\JACK; Project: PB_BUGBASE; RoHS: RoHS; Temperature: -25°C+85°C; Tolerance: NA; Voltage: NA; Wattage: NA; Weight: 1100mg; Datasheet: Y:\MIS_DATABASE\DATASHEETS\CONNECTORS\SJ-4351X-SMT.PDF
R399 = RESISTOR: RES 10K 1/20W 1% 0201; Chkd/date: VASANTHA/270117; Crtd /date: MANIRAJA/270117; Custom_Duty: 15%; Customs_HS_Code: 85332119; Distributor_name: DIGIKEY; Distributor_part_number: 311-10.0KMCT-ND; Footprint Path: Y:\MIS_DATABASE\Library\ALTIUM_TOOL\PCB_FOOTPRINTS\Altium_Footprint_Lib.PcbLib; Height: 0.26MM; Library Path: Y:\MIS_DATABASE\Library\ALTIUM_TOOL\SCHEMATICS_PARTS\MS_DISCRETE_Library.schlib; Mfr_name: YAGEO AMERICA; Mfr_part_number: RC0201FR-0710KL; Mistral Part No: 110011040018-R; Package: 0201; Part_type: RESISTORS\FIXED; Project: GOLDEN-I LITE; RoHS: RoHS; Temperature: -55°C+125°C; Tolerance: 1%; Voltage: NA; Wattage: 1/20W; Weight: 0.17mg; Datasheet: Y:\MIS_DATABASE\DATASHEETS\RESISTORS\RCXXXXL-SER_MAR18.PDF
R404-R407 R448 = RESISTOR: RES 0E 1/20W 5% 0201; Chkd/date: NAVEED/301214; Crtd /date: MUDDU/120710; Custom_Duty: 15%; Customs_HS_Code: 85332119; Distributor_name: DIGIKEY; Distributor_part_number: 311-0.0NCT-ND; Footprint Path: Y:\MIS_DATABASE\Library\ALTIUM_TOOL\PCB_FOOTPRINTS\Altium_Footprint_Lib.PcbLib; Height: 0.26MM; Library Path: Y:\MIS_DATABASE\Library\ALTIUM_TOOL\SCHEMATICS_PARTS\MS_DISCRETE_Library.schlib; Mfr_name: YAGEO AMERICA; Mfr_part_number: RC0201JR-070RL; Mistral Part No: 110010070067-R; Package: 0201; Part_type: RESISTORS\FIXED; Project: PB_BUGBASE; RoHS: RoHS; Temperature: -55°C+125°C; Tolerance: 5%; Voltage: NA; Wattage: 1/20W; Weight: 0.17mg; Datasheet: Y:\MIS_DATABASE\DATASHEETS\RESISTORS\RCXXXXL-SER_MAR18.PDF
R411 R435 = RESISTOR: RES 0E 1/16W JUMPER 0402; Chkd/date: VASANTHA/201216; Crtd /date: MUDDU/190810; Custom_Duty: 15%; Customs_HS_Code: 85332119; Distributor_name: DIGIKEY; Distributor_part_number: 541-0.0JCT-ND; Footprint Path: Y:\MIS_DATABASE\Library\ALTIUM_TOOL\PCB_FOOTPRINTS\Altium_Footprint_Lib.PcbLib; Height: 0.40MM; Library Path: Y:\MIS_DATABASE\Library\ALTIUM_TOOL\SCHEMATICS_PARTS\MS_DISCRETE_Library.schlib; Mfr_name: VISHAY; Mfr_part_number: CRCW04020000Z0ED; Mistral Part No: 110010080019-R; Package: 0402; Part_type: RESISTORS\FIXED; Project: PB_BUGBASE; RoHS: RoHS; Temperature: -55°C+155°C; Tolerance: NA; Voltage: NA; Wattage: 1/16W; Weight: 0.65mg; Datasheet: Y:\MIS_DATABASE\DATASHEETS\RESISTORS\CRCW0603.PDF
R437 = RESISTOR: RES 2.2K 1/20W 1% 0201; Chkd/date: VASANTHA/270117; Crtd /date: MANIRAJA/270117; Custom_Duty: 15%; Customs_HS_Code: 85332119; Distributor_name: DIGIKEY; Distributor_part_number: YAG2572CT-ND; Footprint Path: Y:\MIS_DATABASE\Library\ALTIUM_TOOL\PCB_FOOTPRINTS\Altium_Footprint_Lib.PcbLib; Height: 0.26MM; Library Path: Y:\MIS_DATABASE\Library\ALTIUM_TOOL\SCHEMATICS_PARTS\MS_DISCRETE_Library.schlib; Mfr_name: YAGEO AMERICA; Mfr_part_number: RC0201FR-072K2L; Mistral Part No: 110017010016-R; Package: 0201; Part_type: RESISTORS\FIXED; Project: GOLDEN-I LITE; RoHS: RoHS; Temperature: -55°C+125°C; Tolerance: 1%; Voltage: NA; Wattage: 1/20W; Weight: 0.17mg; Datasheet: Y:\MIS_DATABASE\DATASHEETS\RESISTORS\RCXXXXL-SER_MAR18.PDF
TP59 TP60 TP64 = TESTPOINT: TESTPOINT 1.0MM DRILL PTH; Chkd/date: MAZHAR/271211; Crtd /date: SHREESHAIL/041005; Distributor_name: NA; Distributor_part_number: NA; Height: NA; Mfr_name: LOCAL; Mistral Part No: 130009030938; Package: THRU-HOLE; Project: HSE; Datasheet: NA
U86 = OSC4_KC7050K: OSC 12.288MHz CMOS AUTO SMD; Chkd/date: ALVY/310521; Crtd /date: TAMILARASU/310522; Custom_Duty: 24%; Customs_HS_Code: 85437099; Distributor_name: DIGIKEY; Distributor_part_number: 478-MC2016Z12.2880C19XSHCT-ND; Footprint Path: Y:\MIS_DATABASE\Library\ALTIUM_TOOL\PCB_FOOTPRINTS\Altium_Footprint_Lib.PcbLib; Height: 0.80MM; Library Path: Y:\MIS_DATABASE\Library\ALTIUM_TOOL\SCHEMATICS_PARTS\MS_DISCRETE_Library.schlib; Mfr_name: KYOCERA; Mfr_part_number: MC2016Z12.2880C19XSH; Mistral Part No: 130022050049-R; Package: SMD; Part_type: OSCILLATORS; Project: TI_AM62A_SK_EVM; RoHS: RoHS; Temperature: -40°C+125°C; Tolerance: NA; Voltage: NA; Wattage: NA; Weight: NA; Datasheet: Y:\MIS_DATABASE\DATASHEETS\MISC\CRY_OSC\MC-Z-SER.PDF
U88 = TLV320AIC3106IRGZT_VQFN48: IC LOW-POWER STEREO AUDIO CODEC VQFN48; Chkd/date: SUHAS/261010; Crtd /date: MUDDU/150610; Custom_Duty: 15%; Customs_HS_Code: 85423100; Distributor_name: DIGIKEY; Distributor_part_number: TLV320AIC3106IRGZT-ND; Height: 1.00MM; Mfr_name: TEXAS INSTRUMENTS; Mistral Part No: 143010060003-R; Package: VQFN48; Part_type: ICS\TELECOM\CODEC; Project: CENTAURUS; RoHS: Sb/ Br FREE; Temperature: -40°C+85°C; Weight: NA; Datasheet: Y:\MIS_DATABASE\DATASHEETS\ICS\TELECOM\TLV320AIC3106IRGZT.PDF
U93 = SN74LVC1G08DBVRE4_SOT23-5: IC SINGLE 2-INPUT POSITIVE AND GATE SOT23-5; Chkd/date: SUHAS/221010; Crtd /date: USMAN/151008; Custom_Duty: 15%; Customs_HS_Code: 85423100; Distributor_name: DIGIKEY; Distributor_part_number: SN74LVC1G08DBVRE4-ND; Height: 1.45MM; Mfr_name: TEXAS INSTRUMENTS; Mistral Part No: 141009060026-R; Part_type: ICS\DIGITAL\GATES; Project: KHAN_MAIN; RoHS: Sb/ Br FREE; Temperature: -40°C+85°C; Datasheet: Y:\MIS_DATABASE\DATASHEETS\ICS\DIGITAL\GATES\SN74LVC1G08.PDF
C1 C435 = CAP: CAP CERAMIC 0.01uF 25V 10% X5R 0201; Chkd/date: MANIRAJA/230118; Crtd /date: MANIRAJA/230118; Custom_Duty: 15%; Customs_HS_Code: 85322990; Distributor_name: DIGIKEY; Distributor_part_number: GRM033R61E103KA12J-ND; Footprint Path: Y:\MIS_DATABASE\Library\ALTIUM_TOOL\PCB_FOOTPRINTS\Altium_Footprint_Lib.PcbLib; Height: 0.33MM; Library Path: Y:\MIS_DATABASE\Library\ALTIUM_TOOL\SCHEMATICS_PARTS\MS_DISCRETE_Library.schlib; Mfr_name: MURATA; Mfr_part_number: GRM033R61E103KA12J; Mistral Part No: 120018010007-R; Package: 0201; Part_type: CAPACITORS\CERAMIC; Project: TI_MAXIE_CPB; RoHS: RoHS; Temperature: -55°C+85°C; Tolerance: 10%; Voltage: 25V; Wattage: NA; Weight: 0.33mg; Datasheet: Y:\MIS_DATABASE\DATASHEETS\CAPACITORS\GRM033R61E103KA12.PDF
J12 = HEADER_2X1: CON HDR 1X2 2.54MM PITCH ST TH; Chkd/date: NAVEED/210714; Crtd /date: USMAN/031012; Custom_Duty: 24%; Customs_HS_Code: 85369090; Distributor_name: DIGIKEY; Distributor_part_number: WM8072-ND; Footprint Path: Y:\MIS_DATABASE\Library\ALTIUM_TOOL\PCB_FOOTPRINTS\Altium_Footprint_Lib.PcbLib; Height: 5.60MM; Library Path: Y:\MIS_DATABASE\Library\ALTIUM_TOOL\SCHEMATICS_PARTS\MS_CONNECTOR_Library.schlib; Mfr_name: MOLEX; Mfr_part_number: 90120-0122; Mistral Part No: 150012100005-R; Package: THRU-HOLE; Part_type: CONNECTOR\HEADERS; Project: NPOL_FEP; RoHS: RoHS; Temperature: -55°C+125°C; Tolerance: NA; Voltage: NA; Wattage: NA; Weight: 122mg; Datasheet: Y:\MIS_DATABASE\DATASHEETS\CONNECTORS\90120-XX.PDF
R19 = RESISTOR: RES 8.2K 1/20W 1% 0201; Chkd/date: SUHAS/230910; Crtd /date: MUDDU/060710; Custom_Duty: 15%; Customs_HS_Code: 85332119; Distributor_name: DIGIKEY; Distributor_part_number: 541-8.20KAABCT-ND; Footprint Path: Y:\MIS_DATABASE\Library\ALTIUM_TOOL\PCB_FOOTPRINTS\Altium_Footprint_Lib.PcbLib; Height: 0.28MM; Library Path: Y:\MIS_DATABASE\Library\ALTIUM_TOOL\SCHEMATICS_PARTS\MS_DISCRETE_Library.schlib; Mfr_name: VISHAY; Mfr_part_number: CRCW02018K20FKED; Mistral Part No: 110010070001-R; Package: 0201; Part_type: RESISTORS\FIXED; Project: PB_BUGBASE; RoHS: RoHS; Temperature: -55°C+155°C; Tolerance: 1%; Voltage: NA; Wattage: 1/20W; Weight: 0.17mg; Datasheet: Y:\MIS_DATABASE\DATASHEETS\RESISTORS\CRCW0201.PDF
R451 = RESISTOR: RES 47K 1/20W 5% 0201; Chkd/date: MAZHAR/121207; Crtd /date: USMAN/121207; Custom_Duty: 15%; Customs_HS_Code: 85332119; Distributor_name: DIGIKEY; Distributor_part_number: P47KAGCT-ND; Footprint Path: Y:\MIS_DATABASE\Library\ALTIUM_TOOL\PCB_FOOTPRINTS\Altium_Footprint_Lib.PcbLib; Height: 0.26MM; Library Path: Y:\MIS_DATABASE\Library\ALTIUM_TOOL\SCHEMATICS_PARTS\MS_DISCRETE_Library.schlib; Mfr_name: PANASONIC-ECG; Mfr_part_number: ERJ-1GEJ473C; Mistral Part No: 110009030881-R; Package: 0201; Part_type: RESISTORS\FIXED; Project: SD_WATERLOO; RoHS: RoHS; Temperature: -55°C+125°C; Tolerance: 5%; Voltage: NA; Wattage: 1/20W; Weight: 0.15mg; Datasheet: Y:\MIS_DATABASE\DATASHEETS\RESISTORS\PAN-ERJXGE-FEB06.PDF
TP2-TP7 = TESTPOINT: TESTPOINT CIR 20 SMD; Chkd/date: SHREESHAIL/171006; Crtd /date: MAZHAR/171006; Custom_Duty: NA; Customs_HS_Code: NA; Distributor_name: NA; Distributor_part_number: NA; Footprint Path: Y:\MIS_DATABASE\Library\ALTIUM_TOOL\PCB_FOOTPRINTS\Altium_Footprint_Lib.PcbLib; Height: NA; Library Path: Y:\MIS_DATABASE\Library\ALTIUM_TOOL\SCHEMATICS_PARTS\MS_DISCRETE_Library.schlib; MECHANICAL 3D STEP FILE: NA; Manufacturer: LOCAL; Mfr_name: LOCAL; Mistral Part No: NA; Package: SMD; Project: BT MODULE_CSRBC04; RoHS: NA; Temperature: NA; Tolerance: NA; Voltage: NA; Wattage: NA; Weight: NA; Datasheet: NA
U2 U92 = TCA6424ARGJR_QFN32: IC I2C I/O EXPANDER 24B UQFN32; Chkd/date: NAVEED/100715; Crtd /date: NAVEED/100914; Custom_Duty: 15%; Customs_HS_Code: 85423100; Distributor_name: DIGIKEY; Distributor_part_number: 296-27844-1-ND; Height: 0.60MM; Mfr_name: TEXAS INSTRUMENTS; Mistral Part No: 141014090009-R; Package: UQFN32; Part_type: ICS\DIGITAL\BUSTRANSCEIVER; Project: ZK_BIOMETRIC; RoHS: RoHS; Temperature: -40°C+85°C; Weight: NA; Datasheet: Y:\MIS_DATABASE\DATASHEETS\ICS\DIGITAL\BUSTRANSCEIVER\TCA6424AR.PDF
U51 = TXB0104RUTR_UQFN12: IC 4-BIT BIDIRECTIONAL VOLTAGE-LEVEL TRANSLATOR UQFN12; Chkd/date: MANIRAJA/281117; Crtd /date: ALVY/271117; Custom_Duty: 15%; Customs_HS_Code: 85423100; Distributor_name: DIGIKEY; Distributor_part_number: 296-25888-1-ND; Height: 0.55MM; Manufacturer: TEXAS INSTRUMENTS; Mfr_name: TEXAS INSTRUMENTS; Mistral Part No: 141017110007-R; Package: UQFN12; Part_type: ICS\INTERFACE\LEVEL TRANSLATOR; Project: RSAPR_TYPE-II_3U-SBC; RoHS: RoHS; Temperature: -40°C+85°C; Tolerance: NA; Voltage: NA; Wattage: NA; Weight: 4.70mg; Datasheet: Y:\MIS_DATABASE\DATASHEETS\ICS\INTERFACE\TXB0104.PDF
U52 = SN74CB3Q3257PWR_TSSOP16: IC 4BIT 1-OF-2 FET MULTIPLEXER/DEMULTIPLEXER TSSOP16; Chkd/date: SUHAS/251010; Crtd /date: USMAN/060109; Custom_Duty: 15%; Customs_HS_Code: 85423100; Distributor_name: DIGIKEY; Distributor_part_number: 296-19138-1-ND; Height: 1.20MM; Manufacturer: TEXAS INSTRUMENTS; Mfr_name: TEXAS INSTRUMENTS; Mistral Part No: 141009030117-R; Package: TSSOP16; Part_type: ICS\DIGITAL\COMBINATIONAL; Project: OMAP_EVM; RoHS: Sb/ Br FREE; Temperature: -40°C+85°C; Datasheet: Y:\MIS_DATABASE\DATASHEETS\ICS\DIGITAL\COMBINATIONAL\SN74CB3Q3257.PDF
U18 = AM62A-EVM_SOC_FCBGA484: IC AM62A SK EVM SoC MICROPROCESSOR FCBGA484; Chkd/date: PRADEEP/020823; Crtd /date: PRADEEP/020823; Custom_Duty: 15%; Customs_HS_Code: 85423100; Distributor_name: NA; Distributor_part_number: NA; Footprint Path: Y:\MIS_DATABASE\Library\ALTIUM_TOOL\PCB_FOOTPRINTS\Altium_Footprint_Lib.PcbLib; Height: 2.65MM; Library Ref: AM62A-EVM_SoC_FCBGA484; Mfr_name: TEXAS INSTRUMENTS; Mistral Part No: 141230080001-R; Package: FCBGA484; Part_type: ICS\DIGITAL\MICROPROCESSOR; Project: TI_AM62A_SK_EVM; RoHS: NA; Temperature: NA; Tolerance: NA; Voltage: NA; Wattage: NA; Weight: NA; Datasheet: Y:\MIS_DATABASE\DATASHEETS\ICS\DIGITAL\MICROCONTROLLER\AM62A_SK_EVM.PDF

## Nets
DGND: C1.1 C4.2 C5.1 C7.2 C8.2 C10.1 C13.1 C115.2 C119.2 C124.2 C125.2 C168.2 C169.2 C170.2 C171.2 C172.1 C173.1 C174.1 C175.2 C187.2 C188.1 C402.2 C406.2 C407.2 C409.2 C411.2 C418.2 C419.2 C424.2 C425.2 C434.2 C435.1 J1.12 J1.16 J1.24 J1.SH1 J1.SH2 J1.SH3 J1.SH4 J14.4 J20.1 J20.4 J20.7 J20.10 J20.13 J20.16 J20.19 J20.SH1 J20.SH2 R5.1 R15.2 R18.1 R152.2 R153.2 R159.1 R245.2 R251.2 R253.1 R255.2 R328.1 R432.1 R450.1 R452.1 TP64.1(TP) U2.25(GND) U2.33(EP) U3.2(GND) U5.7(GND) U8.43(EP) U50.4(GND) U51.6(GND) U52.8(GND) U86.2(CASEGND) U88.15(AVSS_ADC) U88.20(DRVSS.1) U88.21(DRVSS.2) U88.26(AVSS_DAC) U88.42(DVSS) U88.43(SELECT) U88.49(TPAD) U92.25(GND) U92.33(EP) U93.3(GND) ; also on sheet 9 10 11 12 13 14 15 16 17 18 19 20 21 22 23 24 25 26 27 28 29 30 31 32 33 34 35 36 40 41 42 43
VCC1V8_SYS: C173.2 R411.2 U51.1(VCCA) ; also on sheet 12 13 17 18 20 33 36 41
VCC3V3_EXP: R293.1 R294.1 ; also on sheet 32
VCC_1V8_AUD: C409.1 C411.1 R411.1 U88.36(DVDD.1)
VCC_3V3_AUD: C124.1 C125.1 C402.1 C406.1 C407.1 C418.1 C419.1 C424.1 C425.1 C434.1 R399.1 R402.1 R403.1 R427.2 R435.1 U86.4(VCC) U88.16(DRVDD.1) U88.17(DRVDD.2) U88.24(DRVDD.3) U88.25(AVDD_DAC) U88.44(IOVDD) U93.5(VCC)
VCC_3V3_SYS: C1.2 C4.1 C5.2 C7.1 C13.2 C169.1 C170.1 C172.2 C174.2 C187.1 C188.2 C435.2 J1.30 J1.32 J1.34 J1.36 J20.22 R1.2 R3.2 R16.1 R17.1 R29.1 R30.1 R31.1 R32.1 R38.1 R39.1 R168.2 R172.2 R252.2 R278.1 R279.1 R292.1 R435.2 R451.2 U2.27(VCCP) U2.31(VCC) U3.7(VCCB) U5.14(VCC) U8.1(VCC) U51.11(VCCB) U52.16(VCC) U92.27(VCCP) U92.31(VCC) ; also on sheet 9 10 12 13 17 18 19 21 22 23 25 26 28 29 30 32 33 34 35 36 40 41 42
VCC_5V0: C171.1 C175.1 U50.2(IN) U50.3(EN2) ; also on sheet 9 10 32 34 40
VCC_CSI_IO: C8.1 C10.2 C168.1 J1.38 J1.40 R4.2 R245.1 R246.1 R247.2 R248.2 R249.1 U3.3(VCCA) ; also on sheet 36
ADDR_IO_EXP: R452.2 U92.26(ADDR)
ADDR_IO_EXP1: R1.1 U2.26(ADDR)
AUD_RSTn: R450.2 U88.33(~{RESET}) U93.4(Y)
AUDIO_MSTRCLK: R407.1 U88.37(MCLK)
BT_EN_SOC: U92.3(P02) ; also on sheet 17
BT_UART_WAKE_SOC_3V3: U92.12(P13) ; also on sheet 17
CSI0_FLEX_RXCLKN: J20.8 U8.28(D0-B)
CSI0_FLEX_RXCLKP: J20.9 U8.29(D0+B)
CSI0_FLEX_RXN0: J20.2 U8.26(D1-B)
CSI0_FLEX_RXN1: J20.5 U8.24(D2-B)
CSI0_FLEX_RXN2: J20.11 U8.22(D3-B)
CSI0_FLEX_RXN3: J20.14 U8.20(CEC_B)
CSI0_FLEX_RXP0: J20.3 U8.27(D1+B)
CSI0_FLEX_RXP1: J20.6 U8.25(D2+B)
CSI0_FLEX_RXP2: J20.12 U8.23(D3+B)
CSI0_FLEX_RXP3: J20.15 U8.21(HPD_B)
CSI0_MIPI_RXCLKN: J1.7 U8.37(D0-A)
CSI0_MIPI_RXCLKP: J1.5 U8.38(D0+A)
CSI0_MIPI_RXN0: J1.11 U8.35(D1-A)
CSI0_MIPI_RXN1: J1.15 U8.33(D2-A)
CSI0_MIPI_RXN2: J1.19 U8.31(D3-A)
CSI0_MIPI_RXN3: J1.23 U8.18(CEC_A)
CSI0_MIPI_RXP0: J1.9 U8.36(D1+A)
CSI0_MIPI_RXP1: J1.13 U8.34(D2+A)
CSI0_MIPI_RXP2: J1.17 U8.32(D3+A)
CSI0_MIPI_RXP3: J1.21 U8.19(HPD_A)
CSI0_RXCLKN: U8.6(D0-) U18.AB14(CSI0_RXCLKN)
CSI0_RXCLKP: U8.5(D0+) U18.AB13(CSI0_RXCLKP)
CSI0_RXN0: U8.8(D1-) U18.W12(CSI0_RXN0)
CSI0_RXN1: U8.11(D2-) U18.Y13(CSI0_RXN1)
CSI0_RXN2: U8.13(D3-) U18.AA13(CSI0_RXN2)
CSI0_RXN3: U8.15(CEC) U18.AB11(CSI0_RXN3)
CSI0_RXP0: U8.7(D1+) U18.W13(CSI0_RXP0)
CSI0_RXP1: U8.10(D2+) U18.Y14(CSI0_RXP1)
CSI0_RXP2: U8.12(D3+) U18.AA12(CSI0_RXP2)
CSI0_RXP3: U8.14(HPD) U18.AB10(CSI0_RXP3)
CSI0_RXRCALIB: R328.2 U18.V10(CSI0_RXRCALIB)
CSI_EN: R292.2 U2.21(P24) U8.2(EN)
CSI_GPIO0: J20.17 U92.14(P15) ; also on sheet 36
CSI_GPIO1: J20.18 U92.15(P16) ; also on sheet 36
CSI_I2C2_nINT1: R29.2 U5.8(~{INT1})
CSI_I2C2_SCL: J20.20 R31.2 U3.8(SCL_B) U5.10(SC1)
CSI_I2C2_SDA: J20.21 R30.2 U3.1(SDA_B) U5.9(SD1)
CSI_I2C_LT_EN: R4.1 R5.2 U3.6(OE)
CSI_MIPI_GPIO0: J1.6 ; also on sheet 36
CSI_MIPI_GPIO1: J1.8 ; also on sheet 36
CSI_MIPI_GPIO2: J1.18 ; also on sheet 36
CSI_MIPI_GPIO3: J1.20 ; also on sheet 36
CSI_MIPI_GPIO4: J1.22 ; also on sheet 36
CSI_MIPI_I2C2_SCL: J1.2 R246.2 U3.5(SCL_A)
CSI_MIPI_I2C2_SDA: J1.4 R249.2 U3.4(SDA_A)
CSI_MIPI_RSTz: J1.14 R255.1 ; also on sheet 36
CSI_REFCLK: J1.10 TP1.1(TP) ; also on sheet 24
CSI_RSTz: U2.10(P11) ; also on sheet 36
CSI_SEL1: R39.2 U8.16(SEL1)
CSI_SEL2: R38.2 U2.20(P23) U8.17(SEL2)
CSI_VLDO_SEL: R251.1 U2.23(P26) U50.1(EN1)
EXP_HAT_DETECT: R172.1 U92.8(P07) ; also on sheet 32
EXP_I2C2_nINT0: R17.2 U5.4(~{INT0})
EXP_I2C2_SCL: R293.2 U5.6(SC0) ; also on sheet 32
EXP_I2C2_SDA: R294.2 U5.5(SD0) ; also on sheet 32
EXP_PS_3V3_EN: U92.6(P05) ; also on sheet 32
EXP_PS_5V0_EN: U92.7(P06) ; also on sheet 32
GPIO1_23_INTn: R448.1 ; also on sheet 41 42
GPIO_AUD_RSTn: R427.1 R432.2 U92.9(P10) U93.1(A)
GPIO_CPSW1_RST: U92.2(P01) ; also on sheet 22
GPIO_CPSW2_RST: U2.19(P22) ; also on sheet 23
GPIO_eMMC_RSTn: U92.10(P11) ; also on sheet 18
GPIO_HDMI_RSTn: U92.13(P14) ; also on sheet 40
HDMI_INTn: U92.17(P20) ; also on sheet 40
HPLOUT: C430.2 J14.2
HPLOUT_C: C430.1 U88.18(HPLOUT)
HPROUT: C431.2 J14.3
HPROUT_C: C431.1 U88.23(HPROUT)
IO_EXP1_INTn: R3.1 U2.32(~{INT})
IO_EXP_INTn: R448.2 R451.1 U92.32(~{INT})
IO_EXP_TEST_LED: U92.24(P27) ; also on sheet 35
LINE1L+: C414.1 TP59.1(TP)
LINE1L+_C: C414.2 U88.3(LINE1L+)
LINE1R+: C416.1 TP60.1(TP)
LINE1R+_C: C416.2 U88.5(LINE1R+)
MCASP1_ACLKX_AUD: TP56.1(TP) U52.3(1B2) U88.38(BCLK)
MCASP1_ACLKX_BT: U51.5(A4) ; also on sheet 17
MCASP1_ACLKX_BUF: U51.7(B4) U52.4(1A) ; also on sheet 31
MCASP1_ACLKX_HDMI: U52.2(1B1) ; also on sheet 40
MCASP1_AFSX_AUD: TP52.1(TP) U52.6(2B2) U88.39(WCLK)
MCASP1_AFSX_BT: U51.4(A3) ; also on sheet 17
MCASP1_AFSX_BUF: U51.8(B3) U52.7(2A) ; also on sheet 31
MCASP1_AFSX_HDMI: U52.5(2B1) ; also on sheet 40
MCASP1_AXR0_AUD: TP57.1(TP) U52.10(3B2) U88.40(DIN)
MCASP1_AXR0_BT: U51.3(A2) ; also on sheet 17
MCASP1_AXR0_BUF: U51.9(B2) U52.9(3A) ; also on sheet 31
MCASP1_AXR0_HDMI: U52.11(3B1) ; also on sheet 40
MCASP1_AXR2_AUD: R404.1 TP51.1(TP) U52.13(4B2)
MCASP1_AXR2_BT: U51.2(A1) ; also on sheet 17
MCASP1_AXR2_BUF: U51.10(B1) U52.12(4A) ; also on sheet 31
MCASP1_BUF_BT_EN: R19.1 U92.20(P23)
MCASP1_BUF_BT_EN_1V8: R18.2 R19.2 U51.12(OE)
MCASP1_FET_EN: R252.1 R253.2 U52.15(~{OE}) U92.19(P22)
MCASP1_FET_SEL: J12.1 R168.1 U52.1(S) U92.21(P24)
MFP0: R152.1 R403.2 U88.45(MFP0)
MFP1: R153.1 R402.2 U88.46(MFP1)
MFP2: TP55.1(TP) U88.47(MFP2)
MFP3: TP54.1(TP) U88.48(MFP3)
MIC_IN: C426.1 J14.1 R437.1 U88.12(MICDET)
MMC1_SD_EN: U92.4(P03) ; also on sheet 19
PD_I2C_IRQ: U92.23(P26) ; also on sheet 9
RESETSTATz: U2.28(~{RESET}) U5.3(~{RESET}) U92.28(~{RESET}) U93.2(B) ; also on sheet 18 19 20 22 23 26 40 41
SOC_I2C1_SCL: R406.1 U2.29(SCL) U92.29(SCL) ; also on sheet 13 21 25 40 41
SOC_I2C1_SDA: R405.1 U2.30(SDA) U92.30(SDA) ; also on sheet 13 21 25 40 41
SoC_I2C2_SCL: R279.2 U5.12(SCL) ; also on sheet 31
SoC_I2C2_SDA: R278.2 U5.13(SDA) ; also on sheet 31
SoC_WLAN_SDIO_RST: U2.24(P27) ; also on sheet 17
SPI0_FET_OE: U2.18(P21) ; also on sheet 41
SPI0_FET_SEL: U2.17(P20) ; also on sheet 41
TEST_GPIO2: U92.18(P21) ; also on sheet 25 27
UART1_FET_BUF_EN: U92.11(P12) ; also on sheet 36
UART1_FET_SEL: U92.22(P25) ; also on sheet 36
VLDO_CSI_1V8: R248.1 U50.5(OUT2)
VLDO_CSI_3V3: R247.1 U50.6(OUT1)
VPP_EN: U92.5(P04) ; also on sheet 12
WL_LT_EN: U2.9(P10) ; also on sheet 17
WLAN_ALERTn: U92.16(P17) ; also on sheet 17
N16929458: TP62.1(TP) U88.7(LINE2L+)
N16929460: TP61.1(TP) U88.8(LINE2L-)
N16929474: R404.2 U88.41(DOUT)
N16929699: C115.1 U88.4(LINE1L-)
N16929703: C119.1 U88.6(LINE1R-)
N16929744: TP67.1(TP) U88.19(HPLCOM)
N16929747: TP66.1(TP) U88.22(HPRCOM)
N16929749: TP102.1(TP) U88.35(GPIO1)
N16929751: TP103.1(TP) U88.34(GPIO2)
N17275147: R407.2 U86.3(OUTPUT)
N17498937: R405.2 U88.2(SDA)
N17498940: R406.2 U88.1(SCL)
N18736007: C426.2 U88.14(MIC3R)
N18736028: R437.2 U88.13(MICBIAS)
N20878915: R16.2 U5.1(A0)
N20878927: R15.1 U5.2(A1)
N20878931: R32.2 U5.11(~{INT})
N20936712: J12.2 R159.2
N21197992: TP7.1(TP) U2.16(P17)
N21197993: TP4.1(TP) U2.15(P16)
N21197994: TP3.1(TP) U2.13(P14)
N21197995: TP6.1(TP) U2.14(P15)
N21197996: TP5.1(TP) U2.12(P13)
N21198784: TP2.1(TP) U2.11(P12)
N23415089: R399.2 U86.1(INH)

Not connected (* = marked no-connect by the designer): J1 1* 3* 25* 26* 27* 28* 29* 31* 33* 35* 37* 39*; U2 1(P00)* 2(P01)* 3(P02)* 4(P03)* 5(P04)* 6(P05)* 7(P06)* 8(P07)* 22(P25)*; U8 3(SCL)* 4(SDA)* 9(NC1) 30(NC2) 39(SDA_B)* 40(SCL_B)* 41(SDA_A)* 42(SCL_A)*; U18 U11(RSVD6)* V11(RSVD7)*; U52 14(4B1)*; U88 9(LINE2R+)* 10(LINE2R-)* 11(MIC3L)* 27(MONO_LO+)* 28(MONO_LO-)* 29(LEFT_LO+)* 30(LEFT_LO-)* 31(RIGHT_LO+)* 32(RIGHT_LO-)*; U92 1(P00)*

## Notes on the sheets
sheet 37
- CSI INTERFACE
- SOC CSI INTERFACE
- 90E
- 90E
- 90E
- 90E
- 90E
- Reserved Pins
- Silk: CSI
- CSI - 1:2  MUX : Truth Table
- MUX_SEL_2
- FUNCTION
- LOW
- INPUT<--A port [CSI-2 Connector - J1]
- MIPI CONNECTOR
- HIGH
- INPUT<--B port [Flex Camera Connector - J20]
- (default)
- [SCL]
- [SDA]
- I2C SWITCH FOR SoC_I2C2
- [GPIO]
- [GPIO]
- [25MHz_REFCLK]
- [RESETz]
- [MOSI/GPIO]
- [SCLK/GPO]
- [CS/GPIO]
- [3V3]
- [VIO]
- R-Note :-
  All the I2C outputs are
  disabled by default
- I2C ADDRESS: 0x71
- MIPI SIDE
- SOC SIDE
- (VCCA < or = VCCB)
- CSI_VLDO_SEL
- LDO VTG
- LOW
- 1.8V (Default)
- Note: 1K res is to bleed off the voltage.
- High
- 3.3V
- Controlled through IO Expander.
sheet 38
- AUDIO CODEC
- Silk: LINE IN
- MIC + HEADPHONE
- D-Note :-
  Add a bulk cap 1 uF
- I2C ADDRESS: 0x1B
- AUDIO CODEC RESET
- CODEC I2C ADDRESS SELECTION
- D-Note :-
  Add a series resistor to the
  SOC GPIO input for isolation
  or testing
  Refer SK-AM62P-LP schematics
- MFP0
- MFP1
- Device Address
- 0
- 0
- 0x18
- 0
- 1
- 0x19
- 1
- 0
- 0x1A
- 1
- 1
- 0x1B
sheet 39
- IO EXPANDER
- I2C ADDRESS: 0x22
- I2C ADDRESS: 0x23
- McASP1 FET SWITCH & BUFFER
- INPUT/OUTPUT
- OEn
- SEL
- An
- L
- H(DEFAULT)
- An=nB2
- MCASP1 - CODEC
- L
- L
- An=nB1
- MCASP1 - HDMI
